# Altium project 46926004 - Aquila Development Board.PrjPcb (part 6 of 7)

## Sheet 160_Power_4.SchDoc: Aquila Development Board
size Letter; Organization: Toradex Solutions Inc.; Address1: 6415 Northwest Drive; Address2: Mississauga, ON, L4V 1X1; Address3: Canada; SheetNumber: 6; SheetTotal: 34
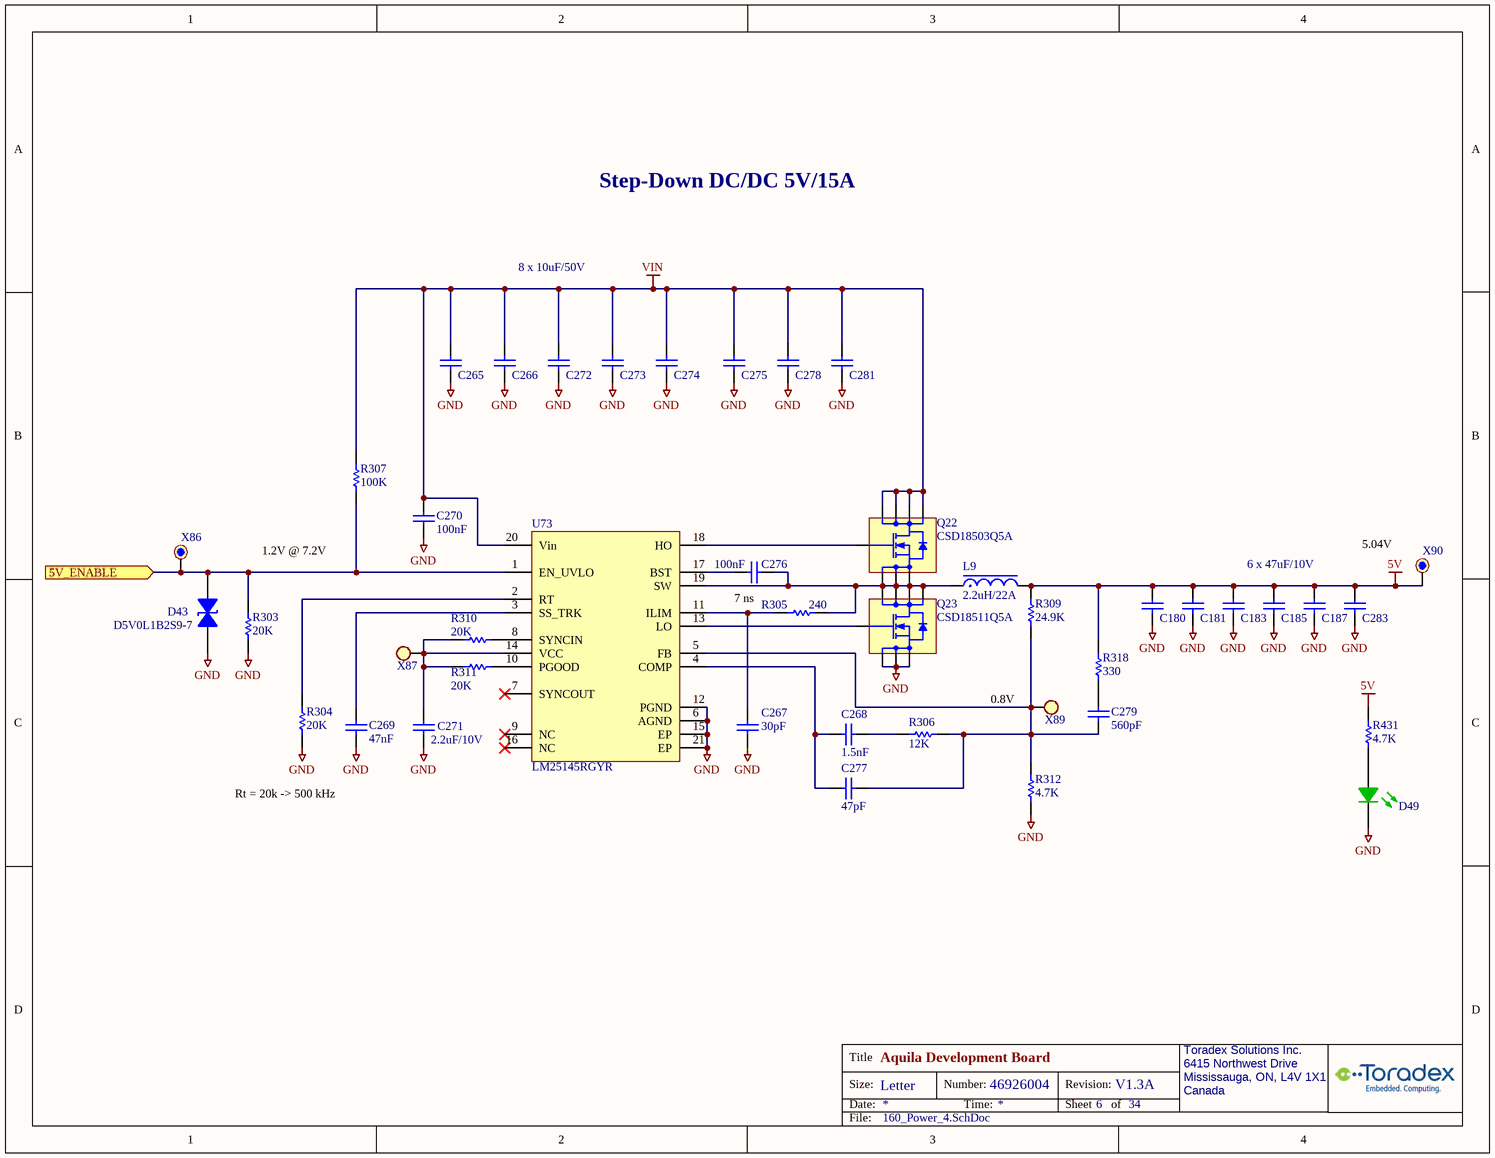
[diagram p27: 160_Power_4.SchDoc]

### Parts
C180  1941-Cap-1206-47uF/10V  [C/1206]  (value not drawn)
C181  1941-Cap-1206-47uF/10V  [C/1206]  (value not drawn)
C183  1941-Cap-1206-47uF/10V  [C/1206]  (value not drawn)
C185  1941-Cap-1206-47uF/10V  [C/1206]  (value not drawn)
C187  1941-Cap-1206-47uF/10V  [C/1206]  (value not drawn)
C265  10uF/50V  [CAPC3225N]  (value not drawn)
C266  10uF/50V  [CAPC3225N]  (value not drawn)
C267  value 30pF  [C0402_CAPC1005L]  (hidden comment: 1554-Cap-0402-30pF)
C268  value 1.5nF  [C0402_CAPC1005L]  (hidden comment: 1573-Cap-0402-1.5nF)
C269  value 47nF  [C/0603]  (hidden comment: 0913-Cap-0603-47nF/50V-X7R)
C270  100nF  [C0402_CAPC1005L]
C271  value 2.2uF/10V  [C0402_CAPC1005L]  (hidden comment: 2234-Cap-0402-2.2uF/10V)
C272  10uF/50V  [CAPC3225N]  (value not drawn)
C273  10uF/50V  [CAPC3225N]  (value not drawn)
C274  10uF/50V  [CAPC3225N]  (value not drawn)
C275  10uF/50V  [CAPC3225N]  (value not drawn)
C276  100nF  [C0402_CAPC1005L]
C277  value 47pF  [C/0603]  (hidden comment: 1567-Cap-0603-47pF/100V)
C278  10uF/50V  [CAPC3225N]  (value not drawn)
C279  value 560pF  [C/0603]  (hidden comment: 1717-Cap-0603-560pF/25V)
C281  10uF/50V  [CAPC3225N]  (value not drawn)
C283  1941-Cap-1206-47uF/10V  [C/1206]  (value not drawn)
D43  D5V0L1B2S9-7  [SOD923_DIO]
D49  Status  [LED-SMT-0603_APT1608CGCK]  (value not drawn)
L9  value 2.2uH/22A  [IND_SRP1265A-LF_BRN]  (hidden comment: 2229-Ind-13.5x12.5-2.2uH/22A)
Q22  CSD18503Q5A  [VSONP-8 (5x6)]
Q23  CSD18511Q5A  [VSONP-8 (5x6)]
R303  value 20K  [R/0603]  (hidden comment: 1216-Res-0603-20K)
R304  value 20K  [R/0603]  (hidden comment: 1216-Res-0603-20K)
R305  value 240  [R0402_RESC1005L]  (hidden comment: 1016-Res-0402-240ohm)
R306  value 12K  [R0402_RESC1005L]  (hidden comment: 1537-Res-0402-12K)
R307  value 100K  [R0402_RESC1005L]  (hidden comment: 1977-Res-0402-100K)
R309  value 24.9K  [R/0603]  (hidden comment: 1144-Res-0603-24.9K)
R310  value 20K  [R/0603]  (hidden comment: 1216-Res-0603-20K)
R311  value 20K  [R/0603]  (hidden comment: 1216-Res-0603-20K)
R312  value 4.7K  [R0402_RESC1005L]  (hidden comment: 2233-Res-0402-4.7K)
R318  value 330  [R0402_RESC1005L]  (hidden comment: 1807-Res-0402-330Ohm)
R431  value 4.7K  [R0402_RESC1005L]  (hidden comment: 2233-Res-0402-4.7K)
U73  LM25145RGYR  [VQFN-20 (3.5x4.5)]
X86  000-TestPoint  [TestPoint_1]  (value not drawn)
X87  000-TestPoint2  [TestPoint_3]  (value not drawn)
X89  000-TestPoint2  [TestPoint_3]  (value not drawn)
X90  000-TestPoint  [TestPoint_1]  (value not drawn)

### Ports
5V_ENABLE (in)

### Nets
5V: C180.2 C181.2 C183.2 C185.2 C187.2 C283.2 L9.2 R309.1 R318.1 R431.2 X90.1
GND: C180.1 C181.1 C183.1 C185.1 C187.1 C265.1 C266.1 C267.2 C269.2 C270.2 C271.1 C272.1 C273.1 C274.1 C275.1 C278.1 C281.1 C283.1 D43.2 D49.2(K) Q23.1(S) Q23.2(S) Q23.3(S) R303.1 R304.1 R312.2 U73.6(AGND) U73.12(PGND) U73.15(EP) U73.21(EP)
VIN: C265.2 C266.2 C270.1 C272.2 C273.2 C274.2 C275.2 C278.2 C281.2 Q22.5(D) Q22.6(D) Q22.7(D) Q22.8(D) R307.2 U73.20(Vin)
5V_ENABLE: D43.1 R303.2 R307.1 U73.1(EN_UVLO) X86.1 ; port 5V_ENABLE
NetC267_1: C267.1 R305.1 U73.11(ILIM)
NetC268_1: C268.1 C277.1 U73.4(COMP)
NetC268_2: C268.2 R306.2
NetC269_1: C269.1 U73.3(SS_TRK)
NetC271_2: C271.2 R310.1 R311.1 U73.14(VCC) X87.1
NetC276_1: C276.1 L9.1 Q22.1(S) Q22.2(S) Q22.3(S) Q23.5(D) Q23.6(D) Q23.7(D) Q23.8(D) R305.2 U73.19(SW)
NetC276_2: C276.2 U73.17(BST)
NetC277_2: C277.2 C279.2 R306.1 R309.2 R312.1 U73.5(FB) X89.1
NetC279_1: C279.1 R318.2
NetD49_1: D49.1(A) R431.1
NetQ22_4: Q22.4(G) U73.18(HO)
NetQ23_4: Q23.4(G) U73.13(LO)
NetR304_2: R304.2 U73.2(RT)
NetR310_2: R310.2 U73.8(SYNCIN)
NetR311_2: R311.2 U73.10(PGOOD)

Not connected (* = marked no-connect by the designer): U73 7(SYNCOUT)* 9(NC)* 16(NC)*

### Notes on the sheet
- Step-Down DC/DC 5V/15A
- 8 x 10uF/50V
- 1.2V @ 7.2V
- 6 x 47uF/10V
- 5.04V
- 7 ns
- (near X89) 0.8V
- Rt = 20k -> 500 kHz

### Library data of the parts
C180 C181 C183 C185 C187 C283 = 1941-Cap-1206-47uF/10V: (-55 to 85 DegC) CAP CER 47UF 10V 20% X5R 1206; MfrNo: CL31A476MPHNNNE; Mfr: Samsung; PN: 1941
C265 C266 C272-C275 C278 C281 = 1607-Cap-1206-10uF/50V: (-55 to 85 DegC) CAP CER 10UF 50V 10% X5R 1206; Mfr: Samsung; MfrNo: CL31A106KBHNNNE; PN: 1607; Alt: CL31A106MBHNNNE,UMK316BBJ106ML-T,UMK316BBJ106KL-T,GRT31CR61H106ME01L,MSASU31LBB5106MTNA01
C267 = 1554-Cap-0402-30pF: (-55 to 125 DegC AEC) CAP CER 30PF 5% 50V C0G/NPO 0402; Mfr: Murata; MfrNo: GCM1555C1H300JA16D; PN: 1554; Alt: AC0402JRNPO9BN300,GCM1555C1H300GA16D,GCM1555C1H300FA16D
C268 = 1573-Cap-0402-1.5nF: (-55 to 125 DegC AEC) CAP CER 1.5nF 10% 50V X7R 0402; Mfr: Taiyo Yuden; MfrNo: UMK105B7152KVHF; Alt: UMK105BJ152KVHF,CL05B152KB5VPNC,GCM155R71H152KA37D; PN: 1573
C269 = 0913-Cap-0603-47nF/50V-X7R: (-55 to 125 DegC) CAP CER 0.047UF 50V X7R 0603; Mfr: TDK Corporation; MfrNo: C1608X7R1H473K080AA; Alt: CL10B473KB8NNNL ,CL10B473KB8NNND,CL10B473KB8SFNC,CL10B473KB8NNNC; PN: 913; Alt2: CL10B473KB8WPNC,CC0603KRX7R9BB473,C1608X7R1H473K080AA,CL10B473KB8NNNC
C270 C276 = 1566-Cap-0402-100nF/50V: (-55 to 125 DegC AEC) Cap Ceramic 0.1uF 50V X7R 10% 0402; MfrNo: GRT155R71H104KE01D; Mfr: Murata; Alt: CL05B104KB54PNC,GCM155R71H104ME02D,GCM155R71H104KE02D,GCM155R71H104KE02J; PN: 1566
C271 = 2234-Cap-0402-2.2uF/10V: (-55 to 85 DegC) CAP CER 2.2UF 10V 20% X5R 0402; Mfr: Yageo; MfrNo: CC0402MRX5R6BB225; PN: 2234
C277 = 1567-Cap-0603-47pF/100V: (-55 to 125 DegC AEC) Cap Ceramic 47pF 100V C0G/NP0 5% SMD 0603; Mfr: Samsung; MfrNo: CL10C470JC81PNC; Alt: C0603C470J1GACAUTO,06031A470J4T2A,GCM1885C2A470JA16D; PN: 1567
C279 = 1717-Cap-0603-560pF/25V: (-55 to 125 DegC) CAP CER 560PF 25V C0G/NPO 0603; Mfr: Yageo; MfrNo: CC0603JRNPO8BN561; PN: 1717
D43 = 1655-D5V0L1B2S9-7: (-65 to 155 DegC) TVS DIODE Vwm:5V Vcl:14V@6A SOD-923; Mfr: Diodes; PN: 1655
D49 = 0333-LED Green 0603: (-40 to 85 DegC) LED GREEN 0603 50mcd; MfrNo: APT1608CGCK; Mfr: Kingbright; Alt: 754-1357-1-ND; Alt2: 160-1834-1-ND; PN: 333; DR: 754-1116-6-ND; DR2: 604-APT1608CGCK
L9 = 2229-Ind-13.5x12.5-2.2uH/22A: (-50 to 150 DegC) FIXED IND 2.2UH 22A 4.2 mOHM 13.5x12.5x6.4mm; Mfr: Bourns; MfrNo: SRP1265A-2R2M; PN: 2229
Q22 = 2196-CSD18503Q5A: (-55 to 150 DegC) MOSFET N-CH 40V 19A Vth:1.8V Ron typ:4.3mohm@10V Vgsm:2.45V 8-VSONP (5x6); Mfr: Texas Instruments; PN: 2196
Q23 = 2195-CSD18511Q5A: (-55 to 150 DegC) MOSFET N-CH 40V 27A Vth:1.8V Ron typ:3.5mohm@4.5V Vgsm:2.45V 8-VSONP (5x6); Mfr: Texas Instruments; MfrNo: CSD18511Q5AT; PN: 2195
R303 R304 R310 R311 = 1216-Res-0603-20K: (-55 to 155 DegC) RES SMD 20K 1% 1/10W 0603 100ppm; Mfr: Bourns; MfrNo: CR0603-FX-2002ELF; Alt: RMCF0603FT20K0,CR0603-FX-2002ELF,RK73H1JTTD2002F,RC0603FR-0720KL; PN: 1216
R305 = 1016-Res-0402-240ohm: (-55 to 155 DegC) RES SMD 240 OHM 1% 1/16W 0402; Mfr: Yageo; MfrNo: RC0402FR-07240RL; Alt: RMCF0402FT240R,RC1005F241CS,AC0402FR-07240RL; PN: 1016; Desc: (-55 to 155 DegC) )RES SMD 240 OHM 1% 1/16W 0402
R306 = 1537-Res-0402-12K: (-55 to 155 DegC AEC) RES 12K OHM 1% 1/16W 100ppm 0402; MfrNo: RMCF0402FT12K0; Mfr: Stackpole Electronics; Alt: AC0402FR-0712KL,CRGCQ0402F12K; PN: 1537
R307 = 1977-Res-0402-100K: (-55 to 155 DegC) RES 100K OHM 1/16W 1% 0402 SMD; Mfr: Yageo; MfrNo: RC0402FR-07100KL; PN: 1977
R309 = 1144-Res-0603-24.9K: (-55 to 155 DegC) RES SMD 24.9K OHM 1% 1/10W 0603 100ppm; MfrNo: RMCF0603FT24K9; Mfr: Stackpole Electronics; Alt: CR0603-FX-2492ELF,RC0603FR-0724K9L; PN: 1144
R312 R431 = 2233-Res-0402-4.7K: (-55 to 155 DegC) RES 4.70K OHM 1/16W 1% 0402 100ppm; MfrNo: RC0402FR-074K7L; Mfr: Yageo; PN: 2233
R318 = 1807-Res-0402-330Ohm: (-55 to 155 DegC AEC) RES 330 OHM 1% 1/16W 100ppm 0402; Mfr: Stackpole Electronics; MfrNo: RMCF0402FT330R; PN: 1807
U73 = 2194-LM25145RGYR: (-40 to 125 DegC) IC REG BUCK 6-42V INPUT 20VFQFN 1MHz; Mfr: Texas Instruments; PN: 2194
X86 X90 = 000-TestPoint: TestPoint TH; Note: this is PCB footprint only, no parts to buy or assemble
X87 X89 = 000-TestPoint2: TestPoint SMD; Note: PCB footprint only, no parts to buy or assemble

## Sheet 510_ISO_CAN.SchDoc: Aquila Development Board
size Letter; Organization: Toradex Solutions Inc.; Address1: 6415 Northwest Drive; Address2: Mississauga, ON, L4V 1X1; Address3: Canada; SheetNumber: 27; SheetTotal: 34
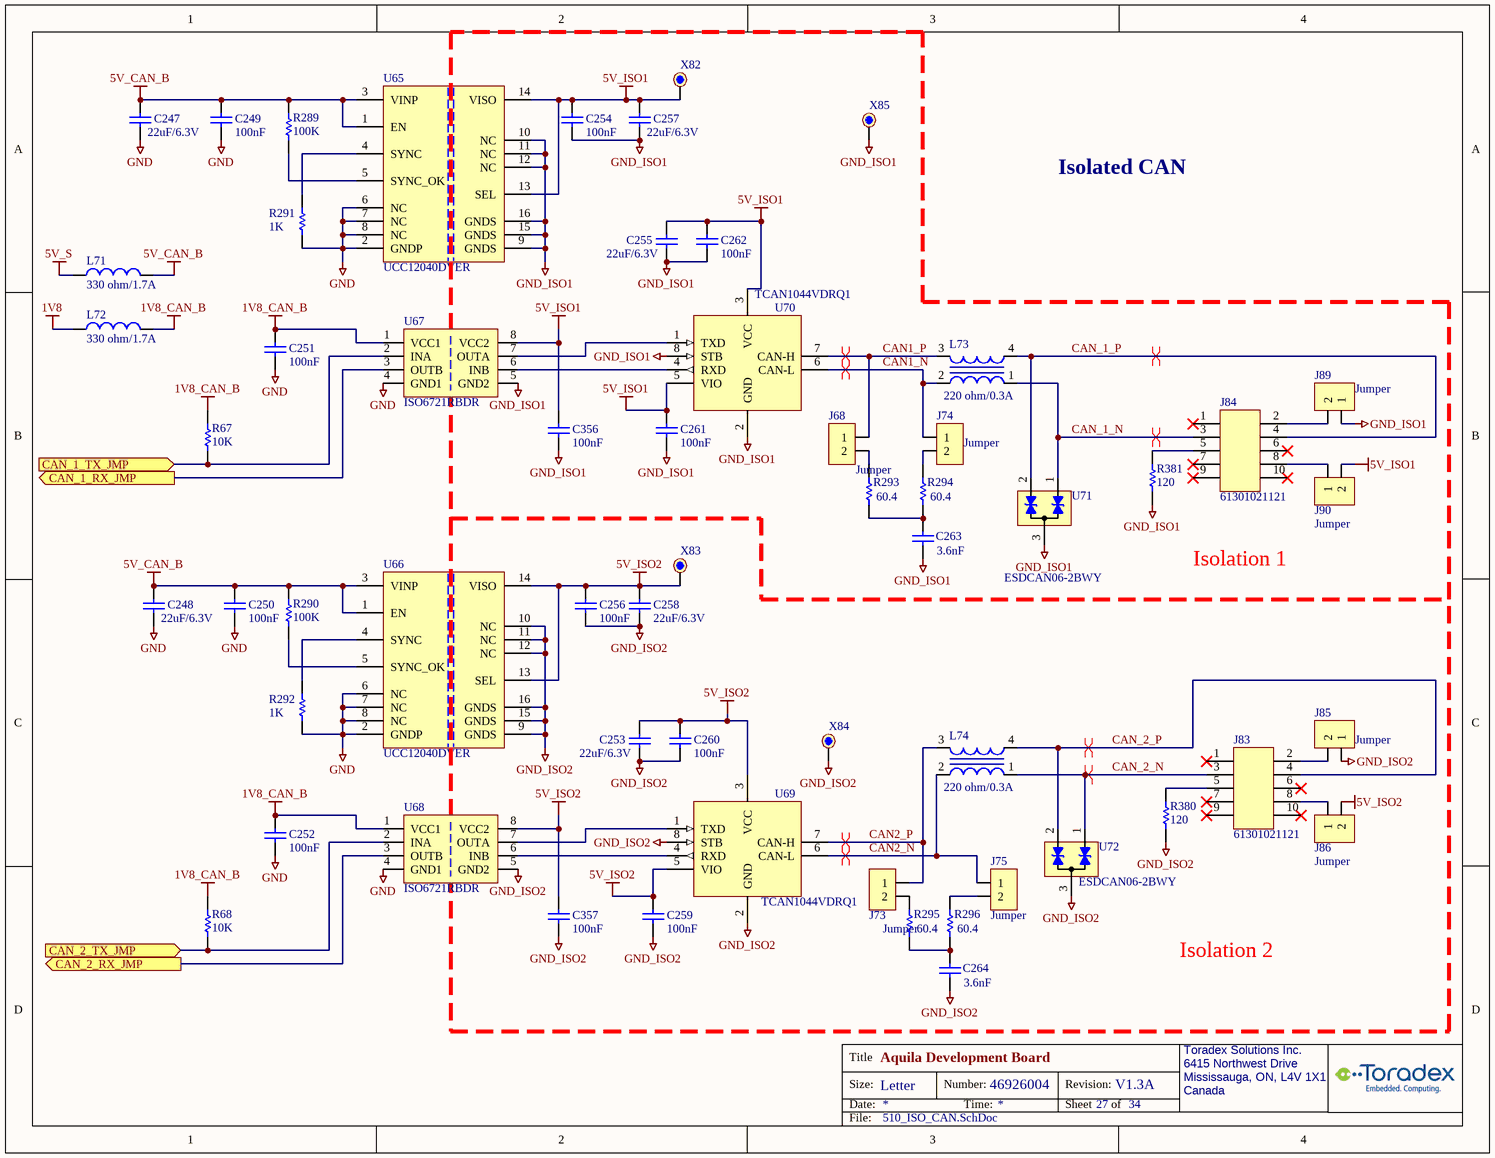
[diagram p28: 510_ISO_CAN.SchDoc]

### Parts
C247  22uF/6.3V  [C0402_CAPC1005L]
C248  22uF/6.3V  [C0402_CAPC1005L]
C249  100nF  [C0402_CAPC1005L]
C250  100nF  [C0402_CAPC1005L]
C251  100nF  [C0402_CAPC1005L]
C252  100nF  [C0402_CAPC1005L]
C253  22uF/6.3V  [C0402_CAPC1005L]
C254  100nF  [C0402_CAPC1005L]
C255  22uF/6.3V  [C0402_CAPC1005L]
C256  100nF  [C0402_CAPC1005L]
C257  22uF/6.3V  [C0402_CAPC1005L]
C258  22uF/6.3V  [C0402_CAPC1005L]
C259  100nF  [C0402_CAPC1005L]
C260  100nF  [C0402_CAPC1005L]
C261  100nF  [C0402_CAPC1005L]
C262  100nF  [C0402_CAPC1005L]
C263  value 3.6nF  [C/0603]  (hidden comment: 1470-Cap-0603-3.6nF)
C264  value 3.6nF  [C/0603]  (hidden comment: 1470-Cap-0603-3.6nF)
C356  100nF  [C0402_CAPC1005L]
C357  100nF  [C0402_CAPC1005L]
J68  67996-200HLF  [CON_HDR1X2]  (value not drawn)
J73  67996-200HLF  [CON_HDR1X2]  (value not drawn)
J74  67996-200HLF  [CON_HDR1X2]  (value not drawn)
J75  67996-200HLF  [CON_HDR1X2]  (value not drawn)
J83  61301021121  [WURTH_61301021121]
J84  61301021121  [WURTH_61301021121]
J85  67996-200HLF  [CON_HDR1X2]  (value not drawn)
J86  67996-200HLF  [CON_HDR1X2]  (value not drawn)
J89  67996-200HLF  [CON_HDR1X2]  (value not drawn)
J90  67996-200HLF  [CON_HDR1X2]  (value not drawn)
L71  value 330 ohm/1.7A  [C/0603]  (hidden comment: 0405-Fer-0603-330ohm/1.7A)
L72  value 330 ohm/1.7A  [C/0603]  (hidden comment: 0405-Fer-0603-330ohm/1.7A)
L73  220 ohm/0.3A  [COMMON_CHOKE_BOURNS_SRF2012-900YA]
L74  220 ohm/0.3A  [COMMON_CHOKE_BOURNS_SRF2012-900YA]
R67  value 10K  [R0402_RESC1005L]  (hidden comment: 1572-Res-0402-10K)
R68  value 10K  [R0402_RESC1005L]  (hidden comment: 1572-Res-0402-10K)
R289  value 100K  [R0402_RESC1005L]  (hidden comment: 1977-Res-0402-100K)
R290  value 100K  [R0402_RESC1005L]  (hidden comment: 1977-Res-0402-100K)
R291  value 1K  [R0402_RESC1005L]  (hidden comment: 1650-Res-0402-1K)
R292  value 1K  [R0402_RESC1005L]  (hidden comment: 1650-Res-0402-1K)
R293  value 60.4  [R/0603]  (hidden comment: 2199-Res-0603-60.4)
R294  value 60.4  [R/0603]  (hidden comment: 2199-Res-0603-60.4)
R295  value 60.4  [R/0603]  (hidden comment: 2199-Res-0603-60.4)
R296  value 60.4  [R/0603]  (hidden comment: 2199-Res-0603-60.4)
R380  value 120  [R0402_RESC1005L]  (hidden comment: 1552-Res-0402-120)
R381  value 120  [R0402_RESC1005L]  (hidden comment: 1552-Res-0402-120)
U65  UCC12040DVER  [SOIC-16]
U66  UCC12040DVER  [SOIC-16]
U67  ISO6721RBDR  [SOIC-8]
U68  ISO6721RBDR  [SOIC-8]
U69  TCAN1044VDRQ1  [SOIC-8]
U70  TCAN1044VDRQ1  [SOIC-8]
U71  ESDCAN06-2BWY  [SOT-323]
U72  ESDCAN06-2BWY  [SOT-323]
X82  000-TestPoint  [TestPoint_1]  (value not drawn)
X83  000-TestPoint  [TestPoint_1]  (value not drawn)
X84  000-TestPoint  [TestPoint_1]  (value not drawn)
X85  000-TestPoint  [TestPoint_1]  (value not drawn)

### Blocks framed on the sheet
Isolation 1: C254 C255 C257 C261-C263 C356 J68 J74 J84 J89 J90 L73 R293 R294 R381 U67 U70 U71 X82 X85

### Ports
CAN_1_RX_JMP (out), CAN_1_TX_JMP (in), CAN_2_RX_JMP (out), CAN_2_TX_JMP (in)

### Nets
1V8: L72.1
1V8_CAN_B: C251.2 C252.2 L72.2 R67.1 R68.1 U67.1(VCC1) U68.1(VCC1)
5V_CAN_B: C247.2 C248.2 C249.2 C250.2 L71.2 R289.2 R290.2 U65.1(EN) U65.3(VINP) U66.1(EN) U66.3(VINP)
5V_ISO1: C254.2 C255.2 C257.2 C261.2 C262.2 C356.2 J90.2 U65.13(SEL) U65.14(VISO) U67.8(VCC2) U70.3(VCC) U70.5(VIO) X82.1
5V_ISO2: C253.2 C256.2 C258.2 C259.2 C260.2 C357.2 J86.2 U66.13(SEL) U66.14(VISO) U68.8(VCC2) U69.3(VCC) U69.5(VIO) X83.1
5V_S: L71.1
GND: C247.1 C248.1 C249.1 C250.1 C251.1 C252.1 R291.1 R292.1 U65.2(GNDP) U65.6(NC) U65.7(NC) U65.8(NC) U66.2(GNDP) U66.6(NC) U66.7(NC) U66.8(NC) U67.4(GND1) U68.4(GND1)
GND_ISO1: C254.1 C255.1 C257.1 C261.1 C262.1 C263.2 C356.1 J89.1 R381.2 U65.9(GNDS) U65.10(NC) U65.11(NC) U65.12(NC) U65.15(GNDS) U65.16(GNDS) U67.5(GND2) U70.2(GND) U70.8(STB) U71.3 X85.1
GND_ISO2: C253.1 C256.1 C258.1 C259.1 C260.1 C264.2 C357.1 J85.1 R380.2 U66.9(GNDS) U66.10(NC) U66.11(NC) U66.12(NC) U66.15(GNDS) U66.16(GNDS) U68.5(GND2) U69.2(GND) U69.8(STB) U72.3 X84.1
CAN1_N: J74.1 L73.2 U70.6(CAN-L)
CAN1_P: J68.1 L73.3 U70.7(CAN-H)
CAN2_N: J75.1 L74.2 U69.6(CAN-L)
CAN2_P: J73.1 L74.3 U69.7(CAN-H)
CAN_1_N: J84.3 L73.1 U71.1
CAN_1_P: J84.4 L73.4 U71.2
CAN_1_RX_JMP: U67.3(OUTB) ; port CAN_1_RX_JMP
CAN_1_TX_JMP: R67.2 U67.2(INA) ; port CAN_1_TX_JMP
CAN_2_N: J83.3 L74.1 U72.1
CAN_2_P: J83.4 L74.4 U72.2
CAN_2_RX_JMP: U68.3(OUTB) ; port CAN_2_RX_JMP
CAN_2_TX_JMP: R68.2 U68.2(INA) ; port CAN_2_TX_JMP
NetC263_1: C263.1 R293.1 R294.1
NetC264_1: C264.1 R295.1 R296.1
NetJ68_2: J68.2 R293.2
NetJ73_2: J73.2 R295.2
NetJ74_2: J74.2 R294.2
NetJ75_2: J75.2 R296.2
NetJ83_2: J83.2 J85.2
NetJ83_5: J83.5 R380.1
NetJ83_8: J83.8 J86.1
NetJ84_2: J84.2 J89.2
NetJ84_5: J84.5 R381.1
NetJ84_8: J84.8 J90.1
NetR289_1: R289.1 U65.5(SYNC_OK)
NetR290_1: R290.1 U66.5(SYNC_OK)
NetR291_2: R291.2 U65.4(SYNC)
NetR292_2: R292.2 U66.4(SYNC)
NetU67_6: U67.6(INB) U70.4(RXD)
NetU67_7: U67.7(OUTA) U70.1(TXD)
NetU68_6: U68.6(INB) U69.4(RXD)
NetU68_7: U68.7(OUTA) U69.1(TXD)

Not connected (* = marked no-connect by the designer): J83 1* 6* 7* 9* 10*; J84 1* 6* 7* 9* 10*

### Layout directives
differential pair; differential pair class CAN: CAN1_N, CAN1_P, CAN2_N, CAN2_P, CAN_1_N, CAN_1_P, CAN_2_N, CAN_2_P

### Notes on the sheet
- Isolated CAN
- (near J89) Jumper
- Jumper
- (near J74) Jumper
- (near J90) Jumper
- (near J85) Jumper
- (near J75) Jumper
- Isolation 2

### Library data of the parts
C247 C248 C253 C255 C257 C258 = 2404-Cap-0402-22uF/6.3V: (-55 to 85 DegC) CAP CER 22UF 6.3V 20% X5R 0402; MfrNo: GRM155R60J226ME11D; Mfr: Murata; PN: 2404
C249-C252 C254 C256 C259-C262 C356 C357 = 1566-Cap-0402-100nF/50V: as C270 on sheet 160_Power_4
C263 C264 = 1470-Cap-0603-3.6nF: (-55 to 125 DegC) CAP CER 3600PF 50V C0G/NP0 0603; Mfr: Murata; MfrNo: GRM1885C1H362JA01D; Alt: GCM1885C1H362FA16J,C0603C362J5GAC7867,C0603C362F5GAC7867; PN: 1470
J68 J73-J75 J85 J86 J89 J90 = 1250-Conn-Hdr-1x2 TH Vert: (-40 to 85 DegC) CONN HDR VERT 1x2 2pos 2.54mm 0.1in Gold no-shroud; Mfr: Amphenol FCI; PN: 1250
J83 J84 = 2237-Conn-Hdr 2x10 2.54MM: (-40 to 105 DegC) CONN HEADER MALE VERT 2x5 10POS 2.54MM TH; Mfr: Wurth Electronics; PN: 2237
L71 L72 = 0405-Fer-0603-330ohm/1.7A: (-55 to 125 DegC) FERRITE BEAD 330 OHM 0603 1.7A 80mohm, typ 48mohm; Mfr: TDK Corporation; MfrNo: MPZ1608S331ATA00; PN: 405; TR: 445-5221-2-ND; DR: 445-5221-6-ND; DR2: 810-MPZ1608S331ATA00
L73 L74 = 1055-Ind-2x1.2-220ohm/0.4A-Choke: (-40 to 125 DegC) INDUCTOR COMMON MODE 220 OHM 0.3A 0.4ohm; MfrNo: SRF2012-221YA; Mfr: Bourns Inc.; PN: 1055; Alt: SRF2012-201YA
R67 R68 = 1572-Res-0402-10K: (-55 to 155 DegC AEC) RES 10K OHM 1% 1/16W 100ppm 0402; MfrNo: RMCF0402FT10K0; Mfr: Stackpole Electronics; Alt: AC0402FR-0710KL,AC0402FR-1310KL,CRGCQ0402F10K; PN: 1572
R289 R290 = 1977-Res-0402-100K: as R307 on sheet 160_Power_4
R291 R292 = 1650-Res-0402-1K: (-55 to 155 DegC AEC) RES 1K OHM 1% 1/16W 100ppm 0402; Mfr: TE Connectivity; MfrNo: CRGCQ0402F1K0; PN: 1650; Alt: CR0402AFX-1001GLF,AC0402FR-131KL,AC0402FR-071KL
R293-R296 = 2199-Res-0603-60.4: (-55 to 155 DegC) RES SMD 60.4 OHM 1% 1/10W 0603; Mfr: Bourns; MfrNo: CR0603-FX-60R4ELF; PN: 2199; Desc: (-55 to 155 DegC) RES SMD 60.4k OHM 1% 1/10W 0603
R380 R381 = 1552-Res-0402-120: (-55 to 155 DegC AEC) RES 120 OHM 1% 1/16W 100ppm 0402; MfrNo: RMCF0402FT120R; Mfr: Stackpole Electronics; PN: 1552; Alt: AC0402FR-07120RL,CRGCQ0402F120R
U65 U66 = 2065-UCC12040DVER: (-40 to 125 DegC) IC Isolated DC DC Converter-Output 3.3V, 5V 140mA, 4.5V-5.5V Input; Mfr: Texas Instruments; PN: 2065
U67 U68 = 2198-ISO6721RBDR: (-40 to 125 DegC) IC DGTL ISO GENERAL-PURPOSE, DUAL-CHANNEL, 1x In, 1x Out 1.71-5.5V; Mfr: Texas Instruments; PN: 2198
U69 U70 = 1620-TCAN1044VDRQ1: (-40 to 125 DegC) IC TXRX CAN FD 8MBPS Vio:1.8-5V Standby 8SOIC; Mfr: Texas Instruments; PN: 1620
U71 U72 = 1564-ESDCAN06-2BWY: (-55 to 175 DegC AEC) TVS DIODE CAN 2-ch 35V Vcl: 59Vmax, 8/20:3A, ESD:30KV air,30KV cont, 15pF, SOT323; Mfr: STMicroelectronics; PN: 1564
X82-X85 = 000-TestPoint: as X86 on sheet 160_Power_4

## Sheet 325_USB_PowerDelivery.SchDoc: Aquila Development Board
size Letter; Organization: Toradex Solutions Inc.; Address1: 6415 Northwest Drive; Address2: Mississauga, ON, L4V 1X1; Address3: Canada; SheetNumber: 18; SheetTotal: 34
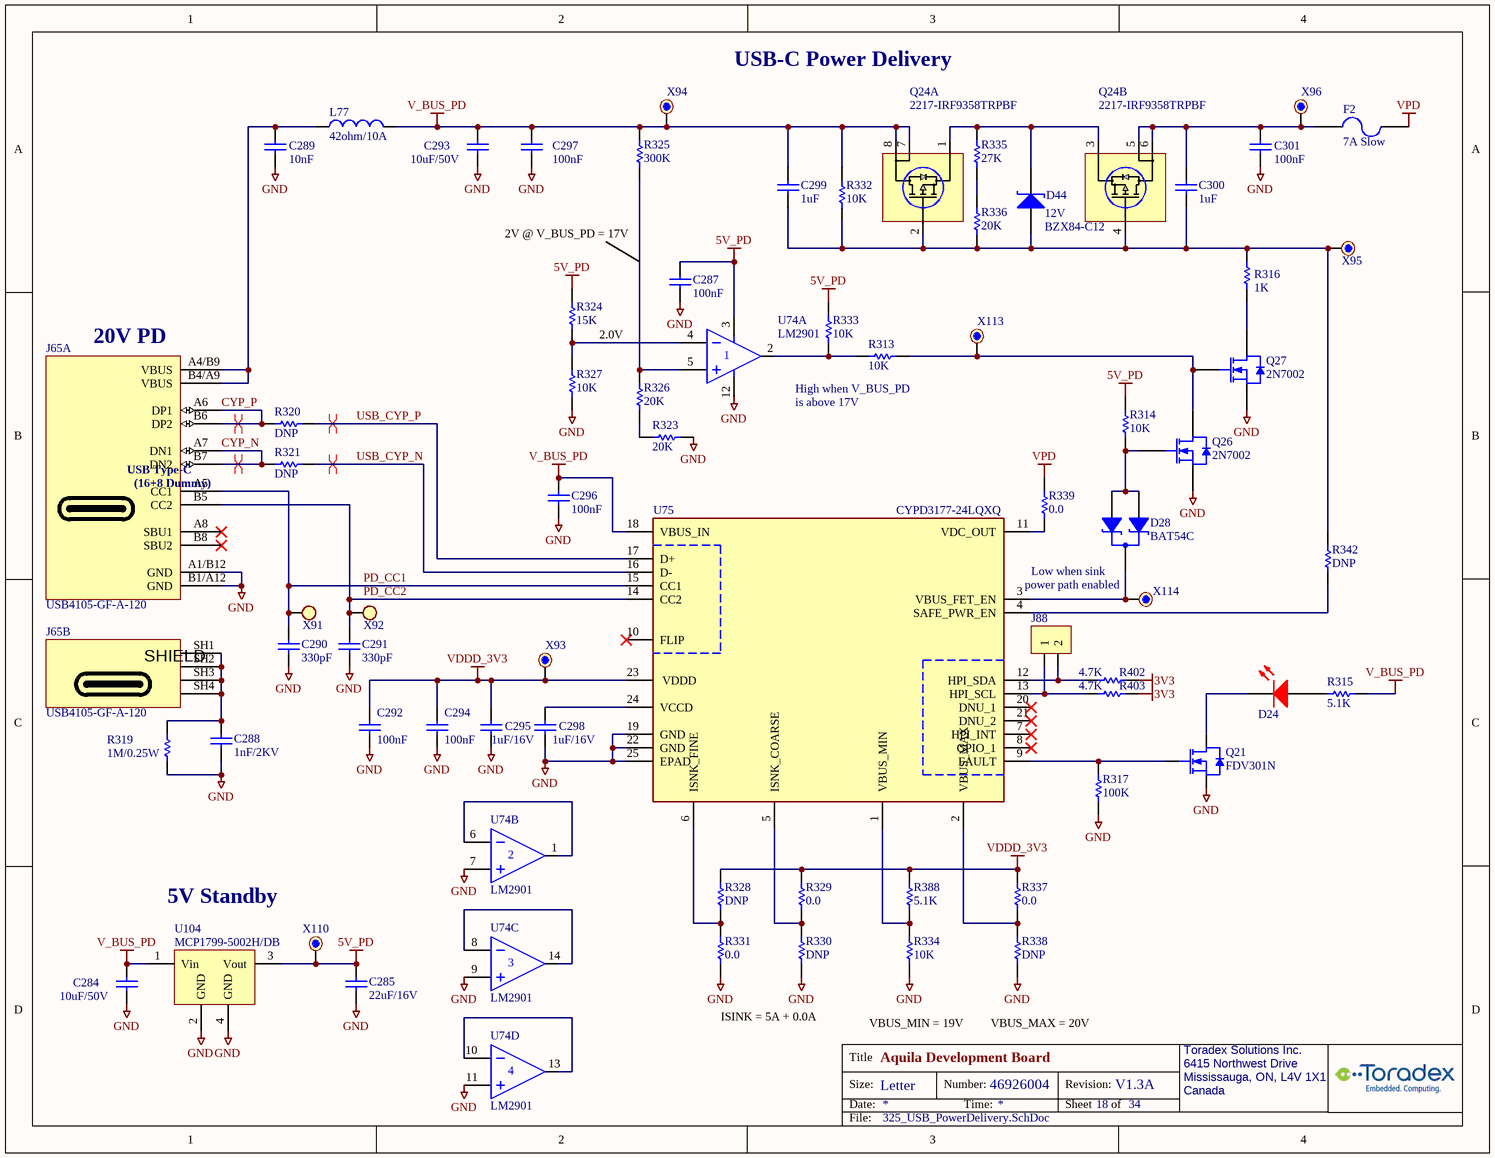
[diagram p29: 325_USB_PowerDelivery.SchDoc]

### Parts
C284  10uF/50V  [CAPC3225N]
C285  value 22uF/16V  [C/0805]  (hidden comment: 1314-Cap-0805-22uF/16V)
C287  100nF  [C0402_CAPC1005L]
C288  value 1nF/2KV  [C/1206]  (hidden comment: 0567-Cap-1206-1nF/2KV)
C289  10nF  [C0402_CAPC1005L]
C290  value 330pF  [C/0603]  (hidden comment: 0105-Cap-0603-330pF/100V)
C291  value 330pF  [C/0603]  (hidden comment: 0105-Cap-0603-330pF/100V)
C292  100nF  [C0402_CAPC1005L]
C293  10uF/50V  [CAPC3225N]
C294  100nF  [C0402_CAPC1005L]
C295  value 1uF/16V  [C0402_CAPC1005L]  (hidden comment: 1644-Cap-0402-1uF/16V)
C296  100nF  [C0402_CAPC1005L]
C297  100nF  [C0402_CAPC1005L]
C298  value 1uF/16V  [C0402_CAPC1005L]  (hidden comment: 1644-Cap-0402-1uF/16V)
C299  value 1uF  [C/0603]  (hidden comment: 1548-Cap-0603-1uF/50V)
C300  value 1uF  [C/0603]  (hidden comment: 1548-Cap-0603-1uF/50V)
C301  100nF  [C0402_CAPC1005L]
D24  Status  [LED-SMT-0603_APT1608CGCK]  (value not drawn)
D28  BAT54C  [SOT23_M]
D44  BZX84-C12  value 12V  [SOT23_N]
F2  7A Slow  [R/1206]
J65  USB4105-GF-A-120  [GCT_USB4105GFA120]  (parts A,B of 2)
J88  000-Hdr-2pin  [HDR1X2]  (value not drawn)  (no BOM)
L77  value 42ohm/10A  [FB_35F0121-0SR-10]  (hidden comment: 1652-Fer-42ohm/10A)
Q21  FDV301N  [SOT23]
Q24  2217-IRF9358TRPBF  [SOIC-8]  (parts A,B of 2)
Q26  2N7002  [SOT23]
Q27  2N7002  [SOT23]
R313  value 10K  [R0402_RESC1005L]  (hidden comment: 1572-Res-0402-10K)
R314  value 10K  [R0402_RESC1005L]  (hidden comment: 1572-Res-0402-10K)
R315  value 5.1K  [R/0603]  (hidden comment: 0227-Res-0603-5.1K)
R316  value 1K  [R0402_RESC1005L]  (hidden comment: 1650-Res-0402-1K)
R317  value 100K  [R0402_RESC1005L]  (hidden comment: 1977-Res-0402-100K)
R319  value 1M/0.25W  [R/1206]  (hidden comment: 1860-Res-1206-1M-5%-0.25W)
R320  value DNP  [R/0603]  (hidden comment: 0000-Res-0603-DNP)
R321  value DNP  [R/0603]  (hidden comment: 0000-Res-0603-DNP)
R323  value 20K  [R/0603]  (hidden comment: 1216-Res-0603-20K)
R324  value 15K  [R0402_RESC1005L]  (hidden comment: 1550-Res-0402-15K)
R325  value 300K  [R/0603]  (hidden comment: 0176-Res-0603-300K)
R326  value 20K  [R/0603]  (hidden comment: 1216-Res-0603-20K)
R327  value 10K  [R0402_RESC1005L]  (hidden comment: 1572-Res-0402-10K)
R328  value DNP  [R/0603]  (hidden comment: 0000-Res-0603-DNP)
R329  value 0.0  [R/0603]  (hidden comment: 0195-Res-0603-0.0ohm)
R330  value DNP  [R/0603]  (hidden comment: 0000-Res-0603-DNP)
R331  value 0.0  [R/0603]  (hidden comment: 0195-Res-0603-0.0ohm)
R332  value 10K  [R0402_RESC1005L]  (hidden comment: 1572-Res-0402-10K)
R333  value 10K  [R0402_RESC1005L]  (hidden comment: 1572-Res-0402-10K)
R334  value 10K  [R0402_RESC1005L]  (hidden comment: 1572-Res-0402-10K)
R335  value 27K  [R0402_RESC1005L]  (hidden comment: 1538-Res-0402-27k)
R336  value 20K  [R/0603]  (hidden comment: 1216-Res-0603-20K)
R337  value 0.0  [R/0603]  (hidden comment: 0195-Res-0603-0.0ohm)
R338  value DNP  [R/0603]  (hidden comment: 0000-Res-0603-DNP)
R339  value 0.0  [R/0603]  (hidden comment: 0195-Res-0603-0.0ohm)
R342  value DNP  [R/0603]  (hidden comment: 0000-Res-0603-DNP)
R388  value 5.1K  [R/0603]  (hidden comment: 0227-Res-0603-5.1K)
R402  value 4.7K  [R0402_RESC1005L]  (hidden comment: 2233-Res-0402-4.7K)
R403  value 4.7K  [R0402_RESC1005L]  (hidden comment: 2233-Res-0402-4.7K)
U74  LM2901  [PW014_N]  (parts A,B,C,D of 4)
U75  CYPD3177-24LQXQ  [IC-Cypress-CYPD3177-24LQXQ]
U104  MCP1799-5002H/DB  [SOT223]
X91  000-TestPoint2  [TestPoint_3]  (value not drawn)
X92  000-TestPoint2  [TestPoint_3]  (value not drawn)
X93  000-TestPoint  [TestPoint_1]  (value not drawn)
X94  000-TestPoint  [TestPoint_1]  (value not drawn)
X95  000-TestPoint  [TestPoint_1]  (value not drawn)
X96  000-TestPoint  [TestPoint_1]  (value not drawn)
X110  000-TestPoint  [TestPoint_1]  (value not drawn)
X113  000-TestPoint  [TestPoint_1]  (value not drawn)
X114  000-TestPoint  [TestPoint_1]  (value not drawn)

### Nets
3V3: R402.1 R403.1
5V_PD: C285.2 C287.2 R314.2 R324.2 R333.2 U74.3(VCC) U104.3(Vout) X110.1
GND: C284.1 C285.1 C287.1 C288.1 C289.1 C290.2 C291.2 C292.1 C293.1 C294.1 C295.1 C296.1 C297.1 C298.1 C301.1 J65.A1/B12(GND) J65.B1/A12(GND) Q21.2(S) Q26.2(S) Q27.2(S) R317.1 R319.2 R323.2 R327.2 R330.1 R331.2 R334.1 R338.1 U74.7(IN+) U74.9(IN+) U74.11(IN+) U74.12(GND) U75.19(GND) U75.22(GND) U75.25(EPAD) U104.2(GND) U104.4(GND)
V_BUS_PD: C284.2 C293.2 C296.2 C297.2 C299.1 L77.2 Q24.7 Q24.8 R315.2 R325.1 R332.2 U75.18(VBUS_IN) U104.1(Vin) X94.1
VDDD_3V3: C292.2 C294.2 C295.2 R328.2 R329.1 R337.2 R388.1 U75.23(VDDD) X93.1
VPD: F2.2 R339.1
CYP_N: J65.A7(DN1) J65.B7(DN2) R321.2
CYP_P: J65.A6(DP1) J65.B6(DP2) R320.2
PD_CC1: C290.1 J65.A5(CC1) U75.15(CC1) X91.1
PD_CC2: C291.1 J65.B5(CC2) U75.14(CC2) X92.1
USB_CYP_N: R321.1 U75.16(D-)
USB_CYP_P: R320.1 U75.17(D+)
NetC288_2: C288.2 J65.SH1(SHIELD) J65.SH2(SHIELD) J65.SH3(SHIELD) J65.SH4(SHIELD) R319.1
NetC289_2: C289.2 J65.A4/B9(VBUS) J65.B4/A9(VBUS) L77.1
NetC298_2: C298.2 U75.24(VCCD)
NetC299_2: C299.2 C300.2 D44.1(A) Q24.2 Q24.4 R316.1 R332.1 R336.1 R342.2 X95.1
NetC300_1: C300.1 C301.2 F2.1 Q24.5 Q24.6 X96.1
NetD24_1: D24.1(A) R315.1
NetD24_2: D24.2(K) Q21.3(D)
NetD28_1: D28.1(A1) D28.2(A2) Q26.1(G) R314.1
NetD28_3: D28.3(K) U75.3(VBUS_FET_EN) X114.1
NetD44_3: D44.3(K) Q24.1 Q24.3 R335.2
NetJ88_1: J88.1 R403.2 U75.13(HPI_SCL)
NetJ88_2: J88.2 R402.2 U75.12(HPI_SDA)
NetQ21_1: Q21.1(G) R317.2 U75.9(FAULT)
NetQ26_3: Q26.3(D) Q27.1(G) R313.1 X113.1
NetQ27_3: Q27.3(D) R316.2
NetR313_2: R313.2 R333.1 U74.2(OUT)
NetR323_1: R323.1 R326.2
NetR324_1: R324.1 R327.1 U74.4(IN-)
NetR325_2: R325.2 R326.1 U74.5(IN+)
NetR328_1: R328.1 R331.1 U75.6(ISNK_FINE)
NetR329_2: R329.2 R330.2 U75.5(ISNK_COARSE)
NetR334_2: R334.2 R388.2 U75.1(VBUS_MIN)
NetR335_1: R335.1 R336.2
NetR337_1: R337.1 R338.2 U75.2(VBUS_MAX)
NetR339_2: R339.2 U75.11(VDC_OUT)
NetR342_1: R342.1 U75.4(SAFE_PWR_EN)
NetU74_1: U74.1(OUT) U74.6(IN-)
NetU74_8: U74.8(IN-) U74.14(OUT)
NetU74_10: U74.10(IN-) U74.13(OUT)

Not connected (* = marked no-connect by the designer): J65 A8(SBU1)* B8(SBU2)*; U75 7(HPI_INT)* 8(GPIO_1)* 10(FLIP)* 20(DNU_1)* 21(DNU_2)*

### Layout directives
differential pair; differential pair class USB_CYP: CYP_N, CYP_P, USB_CYP_N, USB_CYP_P

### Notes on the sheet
- USB-C Power Delivery
- 2V @ V_BUS_PD = 17V
- (near J65) 20V PD
- 2.0V
- High when V_BUS_PD
- is above 17V
- power path enabled
- Low when sink
- 5V Standby
- ISINK = 5A + 0.0A
- VBUS_MIN = 19V
- VBUS_MAX = 20V

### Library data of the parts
C284 C293 = 1607-Cap-1206-10uF/50V: (-55 to 85 DegC) CAP CER 10UF 50V 10% X5R 1206; Mfr: Samsung; MfrNo: CL31A106KBHNNNE; Alt: CL31A106MBHNNNE,UMK316BBJ106ML-T,UMK316BBJ106KL-T,GRT31CR61H106ME01L,MSASU31LBB5106MTNA01; PN: 1607
C285 = 1314-Cap-0805-22uF/16V: (-55 to 85 DegC) CAP CER 22uF 16V X5R 0805; MfrNo: CL21A226MOQNNNE; Mfr: Samsung; PN: 1314; Alt: CL21A226MOCLRNC,CL21A226KOQNNNG,GRM21BR61C226ME44L,EMK212BBJ226MG-T
C287 C292 C294 C296 C297 C301 = 1566-Cap-0402-100nF/50V: as C270 on sheet 160_Power_4
C288 = 0567-Cap-1206-1nF/2KV: (-55 to 125 DegC) CAP CER 1000PF 2KV X7R 1206; Mfr: Johanson Dielectrics Inc.; MfrNo: 202R18W102KV4E; PN: 567; Alt: 478-2956-1-ND; Alt2: 399-4819-1-ND
C289 = 1149-Cap-0402-10nF/50V: (-55 to 125 DegC) Cap Ceramic 10nF 50V X7R 10% 0402; Mfr: Yageo; MfrNo: CC0402KRX7R9BB103; PN: 1149; Alt: CL05B103KB5NNNC,UMK105BJ103KV-F,CL05B103KB5NFNC,0402B103K500CT,CC0402KRX7R9BB103
C290 C291 = 0105-Cap-0603-330pF/100V: (-55 to 125 DegC) CAP CER 330PF 100V 5% NP0 0603; Mfr: Samsung; MfrNo: CL10C331JC8NNNC; Alt: 1276-1073-1-ND; Alt2: 399-1068-1-ND; PN: 105
C295 C298 = 1644-Cap-0402-1uF/16V: (-55 to 85 DegC) CAP CER 1UF 16V 20% X5R 0402; Mfr: Murata; MfrNo: GRM155R61C105MA12D; PN: 1644; Alt: GRM155R61C105KA12D,CL05A105KO5NNNC
C299 C300 = 1548-Cap-0603-1uF/50V: (-55 to 85 DegC AEC) CAP CER 1UF 50V X7R 0603; MfrNo: GRT188R61H105ME13D; Mfr: Murata; PN: 1548; Alt: UMK107ABJ105KAHT,MCASU168AB5105KTNA01,MCASU168AB5105KTNA1J,GRT188R61H105KE13D,UMK107ABJ105MAHT,CGA3E3X5R1H105K080AB
D24 = 1859-LED Red 0603: (-30 to 85 DegC) LED RED 0603 99mcd Vf:2.0V; Mfr: Vishay Lite-On; MfrNo: LTST-C190KRKT; Alt: PN331; PN: 1859
D28 = 0242B-BAT54C: (-55 to 125 DegC) DIODE SCHOTTKY 30V 200MA SOT23, comm. Cathode; Mfr: ON Semi; MfrNo: BAT54CLT1G; Alt: BAT54CFSCT-ND; Alt2: BAT54C-FDICT-ND; PN: 242; TR: BAT54CLT1GOSTR-ND; DR: BAT54CLT1GOSDKR-ND; DR2: 863-BAT54CLT1G
D44 = 0210-BZX84-C12: (-65 to 150 DegC) DIODE ZENER 12V 225MW SOT23-3; Mfr: On Semi; MfrNo: BZX84C12LT1G; PN: 210; Alt: 568-1674-1-ND; Alt2: BZX84C12-TPMSCT-ND
F2 = 1336-Fuse 7A Slow: (-55 to 125 DegC) FUSE SLOW 63VDC 6A 1206 14.5mohm; MfrNo: 0685T6000-01; Mfr: Bel; PN: 1336
J65 = 1660-Conn-USB-Type-C: (-40 to 85 DegC) Conn USB TYPE C RA, 24 (16+8 Dummy) Position, SMT/TH; Mfr: Global Connector Technology; Desc: (-40 to 85 DegC) Conn USB TYPE C RA SMT/TH; PN: 1660
J88 = 000-Hdr-2pin: Header, 2-Pin; Note: PCB footprint only, no parts to buy or assemble
L77 = 1652-Fer-42ohm/10A: (-55 to 125 DegC AEC) FERRITE BEAD 42ohm 10A 0.75mohm 3x3mm SMD; Mfr: Laird Steward; MfrNo: 35F0121-0SR-10; PN: 1652
Q21 = 0761-FDV301N: (-55 to 155 DegC) MOSFET N-CH 25V 220MA SOT-23 Vth:1.1V Ron typ:4ohm@3V Vgsm:8V; Mfr: Fairchild/ON Semiconductor; PN: 761; DR: FDV301NDKR-ND; TR: FDV301NTR-ND; Alt: DMN62D0U-13, DMN62D0U-7, DMN61D9U-7
Q24 = 2217-IRF9358TRPBF: (-55 to 150 DegC) MOSFET 2P-CH 30V 9.2A 8SO; Mfr: Infineon Technologies; PN: 2217
Q26 Q27 = 0030-2N7002: (-55 to 150 DegC AEC) MOSFET N-CH SGL 60V SOT-23 0.3A 1.3ohm@5V; Mfr: NXP; MfrNo: 2N7002P,215; Alt: 2N7002ET1GOSCT-ND; Alt2: 2N7002-FDICT-ND; PN: 30; TR: 568-5818-2-ND; DR: 568-5818-6-ND; DR2: 771-2N7002P-215
R313 R314 R327 R332-R334 = 1572-Res-0402-10K: as R67 on sheet 510_ISO_CAN
R315 R388 = 0227-Res-0603-5.1K: (-55 to 155 DegC) RES 5.1K OHM 1/10W 1% 0603 SMD; Mfr: Rohm; MfrNo: MCR03ERTF5101; Alt: 1276-4713-1-ND; Alt2: 311-5.10KHRCT-ND; PN: 227
R316 = 1650-Res-0402-1K: (-55 to 155 DegC AEC) RES 1K OHM 1% 1/16W 100ppm 0402; MfrNo: CRGCQ0402F1K0; Mfr: TE Connectivity; Alt: CR0402AFX-1001GLF,AC0402FR-131KL,AC0402FR-071KL; PN: 1650
R317 = 1977-Res-0402-100K: as R307 on sheet 160_Power_4
R319 = 1860-Res-1206-1M-5%-0.25W: (-55 to 155 DegC) RES SMD 1M OHM 5% 0.25W 10ppm 1206; Mfr: TE Connectivity; MfrNo: CRGCQ1206J1M0; PN: 1860; Alt: RMCF1206JT1M00, RMCF1206JG1M00, CR1206-JW-105ELF
R320 R321 R328 R330 R338 R342 = 0000-Res-0603-DNP: RES 0603
R323 R326 R336 = 1216-Res-0603-20K: as R303 on sheet 160_Power_4
R324 = 1550-Res-0402-15K: (-55 to 155 DegC AEC) RES 15K OHM 1% 1/16W 100ppm 0402; Mfr: Stackpole Electronics; MfrNo: RMCF0402FT15K0; Alt: AC0402FR-0715KL,CRGCQ0402F15K; PN: 1550
R325 = 0176-Res-0603-300K: (-55 to 155 DegC) RES 300K OHM 1/10W 1% 0603 SMD; Mfr: Yageo; MfrNo: RC0603FR-07300KL; Alt: RHM300KCFCT-ND; Alt2: P300KHCT-ND; PN: 176; TR: 311-300KHRTR-ND
R329 R331 R339 = 0195-Res-0603-0.0ohm: (-55 to 155 DegC) RES 0.0 OHM 1/10W JUMP 0603; Mfr: Samsung; MfrNo: RC1608J000CS; Alt: 311-0.0GRCT-ND; Alt2: A106051CT-ND; PN: 195; TR: 1276-3510-2-ND
R335 = 1538-Res-0402-27k: (-55 to 155 DegC AEC) RES 27K OHM 1% 1/16W 100ppm 0402; Mfr: Stackpole Electronics; MfrNo: RMCF0402FT27K0; PN: 1538; Alt: AC0402FR-0727KL,CRGCQ0402F27K
R337 = 0195-Res-0603-0.0ohm: (-55 to 155 DegC) RES 0.0 OHM 1/10W JUMP 0603; Mfr: Samsung; MfrNo: RC1608J000CS; PN: 195; Alt: 311-0.0GRCT-ND; Alt2: A106051CT-ND; TR: 1276-3510-2-ND
R402 R403 = 2233-Res-0402-4.7K: as R312 on sheet 160_Power_4
U74 = 0236-LM2901: (-40 to 125 DegC) IC COMPARATOR QUAD LP 14-TSSOP 2-30V OC Iq:1.3mAtyp 2.5mAmax Vos:1mVtyp 15mVmax Ib:25nAtyp 400nAmax; Mfr: ST; MfrNo: LM2901PT; Alt: 296-6597-1-ND; PN: 236; DR: 497-6454-6-ND; TR: 497-6454-2-ND; DR2: 511-LM2901P
U75 = 2216-CYPD3177-24LQXQ: (-40 to 125 DegC) IC USB Type C PMIC 20V/5A Max 24-QFN (4x4); Mfr: Infineon Technologies; PN: 2216
U104 = 1666-MCP1799: (-40 to 150 DegC) IC REG LINEAR LDO Vin: 45Vmax Vout:5V fixed 80mA SOT223-3; Mfr: Microchip; MfrNo: MCP1799T-5002H/DB; PN: 1666; Note: same component in tubes: MCP1799-5002H/DB
X91 X92 = 000-TestPoint2: as X87 on sheet 160_Power_4
X93-X96 X110 X113 X114 = 000-TestPoint: as X86 on sheet 160_Power_4

## Sheet 700_RS232_RS485.SchDoc: Aquila Development Board
size Letter; Organization: Toradex Solutions Inc.; Address1: 6415 Northwest Drive; Address2: Mississauga, ON, L4V 1X1; Address3: Canada; SheetNumber: 31; SheetTotal: 34
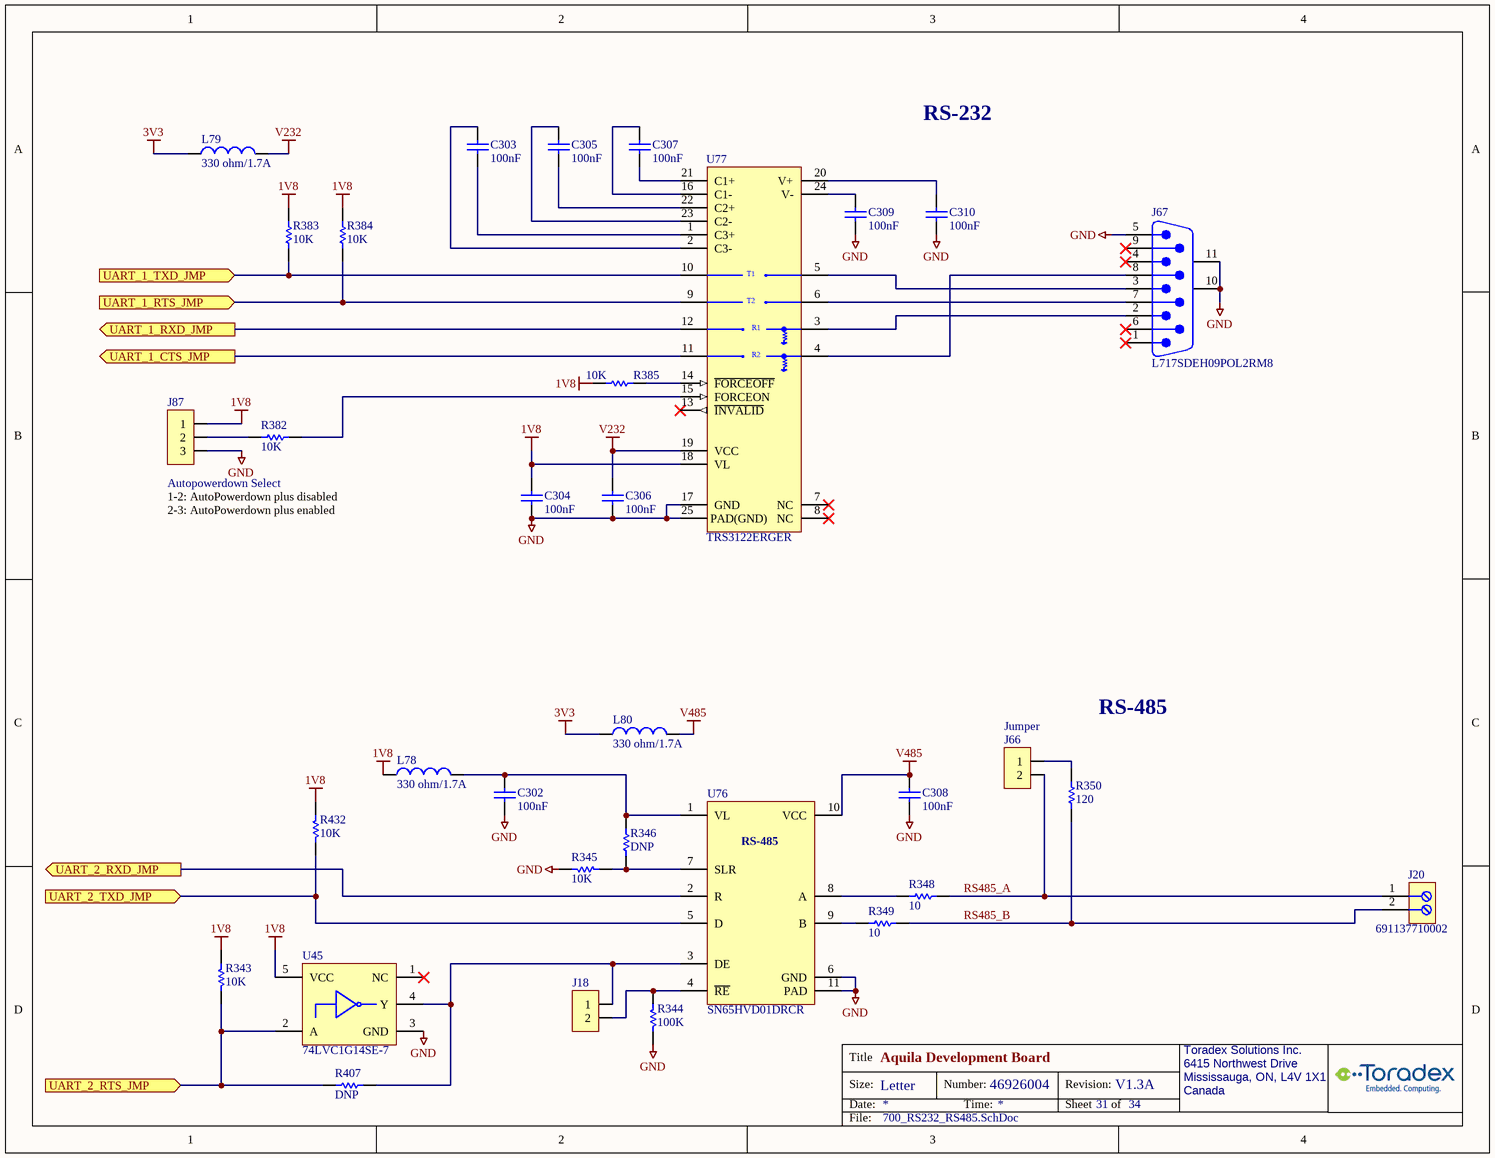
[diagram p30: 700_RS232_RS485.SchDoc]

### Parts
C302  100nF  [C0402_CAPC1005L]
C303  100nF  [C0402_CAPC1005L]
C304  100nF  [C0402_CAPC1005L]
C305  100nF  [C0402_CAPC1005L]
C306  100nF  [C0402_CAPC1005L]
C307  100nF  [C0402_CAPC1005L]
C308  100nF  [C0402_CAPC1005L]
C309  100nF  [C0402_CAPC1005L]
C310  100nF  [C0402_CAPC1005L]
J18  1250-Conn-Hdr-1x2 TH Vert  [CON_HDR1X2]  (value not drawn)
J20  691137710002  [WURTH_691137710002]
J66  67996-200HLF  [CON_HDR1X2]  (value not drawn)
J67  L717SDEH09POL2RM8  [DSUB_A-DS 09 A/KG-T2S]
J87  68001-203HLF  [CON_HDR1X3]  (value not drawn)
L78  value 330 ohm/1.7A  [C/0603]  (hidden comment: 0405-Fer-0603-330ohm/1.7A)
L79  value 330 ohm/1.7A  [C/0603]  (hidden comment: 0405-Fer-0603-330ohm/1.7A)
L80  value 330 ohm/1.7A  [C/0603]  (hidden comment: 0405-Fer-0603-330ohm/1.7A)
R343  value 10K  [R0402_RESC1005L]  (hidden comment: 1572-Res-0402-10K)
R344  value 100K  [R0402_RESC1005L]  (hidden comment: 1977-Res-0402-100K)
R345  value 10K  [R0402_RESC1005L]  (hidden comment: 1572-Res-0402-10K)
R346  value DNP  [R/0603]  (hidden comment: 0000-Res-0603-DNP)
R348  value 10  [R0402_RESC1005L]  (hidden comment: 0257-Res-0402-10ohm)
R349  value 10  [R0402_RESC1005L]  (hidden comment: 0257-Res-0402-10ohm)
R350  value 120  [R0402_RESC1005L]  (hidden comment: 1552-Res-0402-120)
R382  value 10K  [R0402_RESC1005L]  (hidden comment: 1572-Res-0402-10K)
R383  value 10K  [R0402_RESC1005L]  (hidden comment: 1572-Res-0402-10K)
R384  value 10K  [R0402_RESC1005L]  (hidden comment: 1572-Res-0402-10K)
R385  value 10K  [R0402_RESC1005L]  (hidden comment: 1572-Res-0402-10K)
R407  value DNP  [R/0603]  (hidden comment: 0000-Res-0603-DNP)
R432  value 10K  [R0402_RESC1005L]  (hidden comment: 1572-Res-0402-10K)
U45  74LVC1G14SE-7  [SOT353-5N]
U76  SN65HVD01DRCR  [10-VSON (3x3)]
U77  TRS3122ERGER  [QFN4X4-24_EP]

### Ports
UART_1_CTS_JMP (out), UART_1_RTS_JMP (in), UART_1_RXD_JMP (out), UART_1_TXD_JMP (in), UART_2_RTS_JMP (in), UART_2_RXD_JMP (out), UART_2_TXD_JMP (in)

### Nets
1V8: C304.1 J87.1 L78.1 R343.2 R383.2 R384.2 R385.2 R432.2 U45.5(VCC) U77.18(VL)
3V3: L79.1 L80.1
GND: C302.1 C304.2 C306.2 C308.2 C309.2 C310.2 J67.5 J67.10(MH1) J67.11(MH2) J87.3 R344.1 R345.1 U45.3(GND) U76.6(GND) U76.11(PAD) U77.17(GND) U77.25(PAD(GND))
V232: C306.1 L79.2 U77.19(VCC)
V485: C308.1 L80.2 U76.10(VCC)
RS485_A: J20.1 J66.2 R348.1
RS485_B: J20.2 R349.1 R350.2
UART_1_CTS_JMP: U77.11(ROUT2) ; port UART_1_CTS_JMP
UART_1_RTS_JMP: R384.1 U77.9(DIN2) ; port UART_1_RTS_JMP
UART_1_RXD_JMP: U77.12(ROUT1) ; port UART_1_RXD_JMP
UART_1_TXD_JMP: R383.1 U77.10(DIN1) ; port UART_1_TXD_JMP
UART_2_RTS_JMP: R343.1 R407.2 U45.2(A) ; port UART_2_RTS_JMP
UART_2_RXD_JMP: U76.2(R) ; port UART_2_RXD_JMP
UART_2_TXD_JMP: R432.1 U76.5(D) ; port UART_2_TXD_JMP
NetC302_2: C302.2 L78.2 R346.2 U76.1(VL)
NetC303_1: C303.1 U77.2(C3-)
NetC303_2: C303.2 U77.1(C3+)
NetC305_1: C305.1 U77.23(C2-)
NetC305_2: C305.2 U77.22(C2+)
NetC307_1: C307.1 U77.16(C1-)
NetC307_2: C307.2 U77.21(C1+)
NetC309_1: C309.1 U77.24(V-)
NetC310_1: C310.1 U77.20(V+)
NetJ18_1: J18.1 R407.1 U45.4(Y) U76.3(DE)
NetJ18_2: J18.2 R344.2 U76.4(~{RE})
NetJ66_1: J66.1 R350.1
NetJ67_2: J67.2 U77.3(RIN1)
NetJ67_3: J67.3 U77.5(DOUT1)
NetJ67_7: J67.7 U77.6(DOUT2)
NetJ67_8: J67.8 U77.4(RIN2)
NetJ87_2: J87.2 R382.2
NetR345_2: R345.2 R346.1 U76.7(SLR)
NetR348_2: R348.2 U76.8(A)
NetR349_2: R349.2 U76.9(B)
NetR382_1: R382.1 U77.15(FORCEON)
NetR385_1: R385.1 U77.14(~{FORCEOFF})

Not connected (* = marked no-connect by the designer): J67 1* 4* 6* 9*; U45 1(NC)*; U77 7(NC)* 8(NC)* 13(~{INVALID})*

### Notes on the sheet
- RS-232
- Autopowerdown Select
- 1-2: AutoPowerdown plus disabled
- 2-3: AutoPowerdown plus enabled
- (near J66) Jumper
- RS-485

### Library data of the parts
C302-C310 = 1566-Cap-0402-100nF/50V: as C270 on sheet 160_Power_4
J18 = 1250-Conn-Hdr-1x2 TH Vert: (-40 to 85 DegC) CONN HDR VERT 1x2 2pos 2.54mm 0.1in Gold no-shroud; Mfr: Amphenol FCI; MfrNo: 67996-200HLF; PN: 1250
J20 = 2094-Conn-Hdr 1x2 2POS 5MM SCREW TERM: (-30 to 120 DegC) CONN TERM BLK 2POS SIDE ENTRY 5MM SCREW 16A 300V; Mfr: Wurth Electronics; PN: 2094
J66 = 1250-Conn-Hdr-1x2 TH Vert: as J68 on sheet 510_ISO_CAN
J67 = 0760-Conn-DSUB9 Male R/A: (-55 to 105 DegC) CONN D-SUB PLUG 9POS R/A SOLDER Male; MfrNo: A-DS 09 A/KG-T2S; Mfr: Assmann WSW Components; PN: 760
J87 = 2539-Conn-Hdr-1x3 TH Vert: (-65 to 125 DegC) CONN HDR VERT 3x1 3pos 2.54mm 0.1in Gold no-shroud; Mfr: Amphenol ICC / FCI; PN: 2539
L78-L80 = 0405-Fer-0603-330ohm/1.7A: as L71 on sheet 510_ISO_CAN
R343 R345 R382-R385 R432 = 1572-Res-0402-10K: (-55 to 155 DegC AEC) RES 10K OHM 1% 1/16W 100ppm 0402; Mfr: Stackpole Electronics; MfrNo: RMCF0402FT10K0; Alt: AC0402FR-0710KL,AC0402FR-1310KL,CRGCQ0402F10K; PN: 1572
R344 = 1977-Res-0402-100K: as R307 on sheet 160_Power_4
R346 R407 = 0000-Res-0603-DNP: RES 0603
R348 R349 = 0257-Res-0402-10ohm: (-55 to 155 DegC) RES 10 OHM 1/16W 1% 0402 SMD; Mfr: Rohm Semiconductor; MfrNo: MCR01MRTF10R0; Alt: 311-10.0LRCT-ND; Alt2: 1276-3428-1-ND; PN: 257
R350 = 1552-Res-0402-120: (-55 to 155 DegC AEC) RES 120 OHM 1% 1/16W 100ppm 0402; Mfr: Stackpole Electronics; MfrNo: RMCF0402FT120R; PN: 1552; Alt: AC0402FR-07120RL,CRGCQ0402F120R
U45 = 2009-74LVC1G14SE-7: (-40 to 125 DegC) IC INVERTER SCHMITT 1CH 1IN 1.65-5.5V SOT353; Mfr: Diodes; PN: 2009; Desc: (-40 to 125 DegC) IC INVERT SCHMITT 1CH 1IN 1.65-5.5V SOT353
U76 = 2215-SN65HVD01DRCR: (-40 to 125 DegC) IC TRANSCEIVER HALF 1/1, 3V3 RS-485, 1.65V I/O, 10VSON; Mfr: Texas Instruments; PN: 2215
U77 = 2205-TRS3122ERGER: (-40 to 85 DegC) IC TRANSCEIVER RS-232 2/2 24-VQFN (4x4); Mfr: Texas Instruments; PN: 2205; Desc: (-40 to 85 DegC) IC TRANSCEIVER 2/2 24VQFN

## Sheet 315_USBC_DFP.SchDoc: Aquila Development Board
size A3; Organization: Toradex Solutions Inc.; Address1: 6415 Northwest Drive; Address2: Mississauga, ON, L4V 1X1; Address3: Canada; SheetNumber: 17; SheetTotal: 34
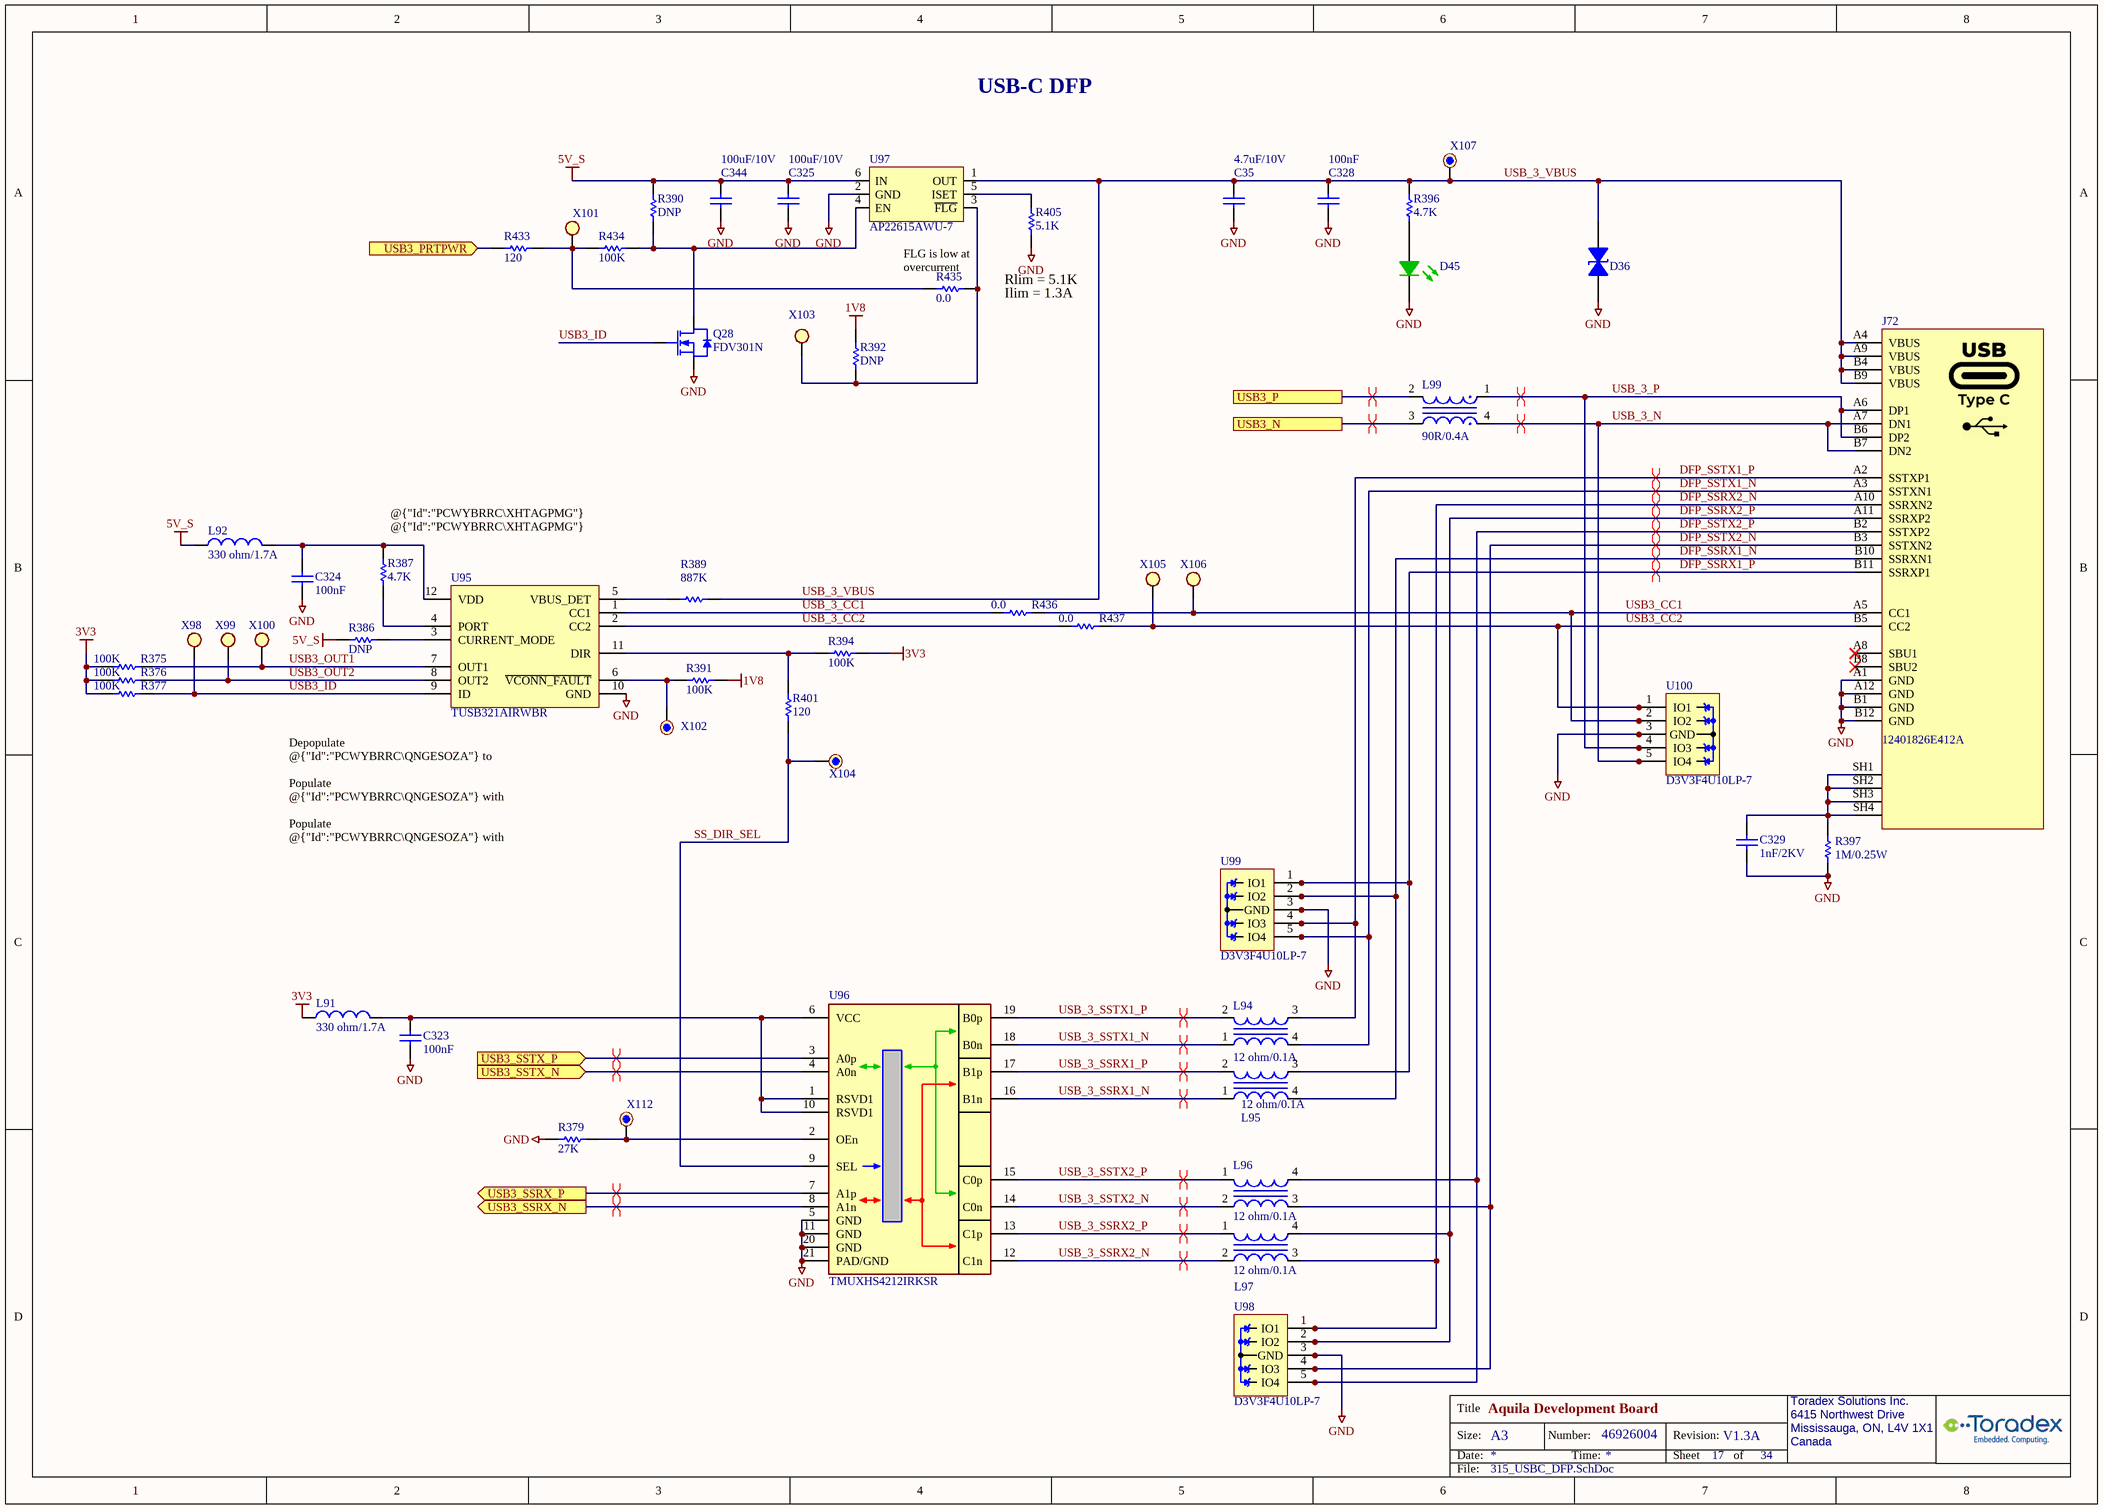
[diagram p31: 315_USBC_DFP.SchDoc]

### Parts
C35  value 4.7uF/10V  [C/0603]  (hidden comment: 2093-Cap-0603-4.7uF/10V)
C323  100nF  [C0402_CAPC1005L]
C324  100nF  [C0402_CAPC1005L]
C325  100uF/10V  [C/1206]
C328  100nF  [C0402_CAPC1005L]
C329  value 1nF/2KV  [C/1206]  (hidden comment: 0567-Cap-1206-1nF/2KV)
C344  100uF/10V  [C/1206]
D36  D5V0L1B2S9-7  [SOD923_DIO]  (value not drawn)
D45  Status  [LED-SMT-0603_APT1608CGCK]  (value not drawn)
J72  12401826E412A  [AMPHENOL_12401826E412A]
L91  value 330 ohm/1.7A  [C/0603]  (hidden comment: 0405-Fer-0603-330ohm/1.7A)
L92  value 330 ohm/1.7A  [C/0603]  (hidden comment: 0405-Fer-0603-330ohm/1.7A)
L94  12 ohm/0.1A  [COIL0302]
L95  12 ohm/0.1A  [COIL0302]
L96  12 ohm/0.1A  [COIL0302]
L97  12 ohm/0.1A  [COIL0302]
L99  90R/0.4A  [COMMON_CHOKE_BOURNS_SRF2012-900YA]
Q28  FDV301N  [SOT23]
R375  value 100K  [R0402_RESC1005L]  (hidden comment: 1977-Res-0402-100K)
R376  value 100K  [R0402_RESC1005L]  (hidden comment: 1977-Res-0402-100K)
R377  value 100K  [R0402_RESC1005L]  (hidden comment: 1977-Res-0402-100K)
R379  value 27K  [R0402_RESC1005L]  (hidden comment: 1538-Res-0402-27k)
R386  value DNP  [R/0603]  (hidden comment: 0000-Res-0603-DNP)
R387  value 4.7K  [R0402_RESC1005L]  (hidden comment: 2233-Res-0402-4.7K)
R389  value 887K  [R0402_RESC1005L]  (hidden comment: 1809-Res-0402-887K)
R390  value DNP  [R/0603]  (hidden comment: 0000-Res-0603-DNP)
R391  value 100K  [R0402_RESC1005L]  (hidden comment: 1977-Res-0402-100K)
R392  value DNP  [R0402_RESC1005L]  (hidden comment: 0000-Res-0402-DNP)
R394  value 100K  [R0402_RESC1005L]  (hidden comment: 1977-Res-0402-100K)
R396  value 4.7K  [R0402_RESC1005L]  (hidden comment: 2233-Res-0402-4.7K)
R397  value 1M/0.25W  [R/1206]  (hidden comment: 1860-Res-1206-1M-5%-0.25W)
R401  value 120  [R0402_RESC1005L]  (hidden comment: 1552-Res-0402-120)
R405  value 5.1K  [R/0603]  (hidden comment: 0227-Res-0603-5.1K)
R433  value 120  [R0402_RESC1005L]  (hidden comment: 1552-Res-0402-120)
R434  value 100K  [R0402_RESC1005L]  (hidden comment: 1977-Res-0402-100K)
R435  value 0.0  [R/0603]  (hidden comment: 0195-Res-0603-0.0ohm)
R436  value 0.0  [R/0603]  (hidden comment: 0195-Res-0603-0.0ohm)
R437  value 0.0  [R/0603]  (hidden comment: 0195-Res-0603-0.0ohm)
U95  TUSB321AIRWBR  [12-X2QFN (1.6x1.6)]
U96  TMUXHS4212IRKSR  [VQFN-20 (4.5x2.5)]
U97  AP22615AWU-7  [TSOT26]
U98  D3V3F4U10LP-7  [10-UFDFN]
U99  D3V3F4U10LP-7  [10-UFDFN]
U100  D3V3F4U10LP-7  [10-UFDFN]
X98  000-TestPoint2  [TestPoint_3]  (value not drawn)
X99  000-TestPoint2  [TestPoint_3]  (value not drawn)
X100  000-TestPoint2  [TestPoint_3]  (value not drawn)
X101  000-TestPoint2  [TestPoint_3]  (value not drawn)
X102  000-TestPoint  [TestPoint_1]  (value not drawn)
X103  000-TestPoint2  [TestPoint_3]  (value not drawn)
X104  000-TestPoint  [TestPoint_1]  (value not drawn)
X105  000-TestPoint2  [TestPoint_3]  (value not drawn)
X106  000-TestPoint2  [TestPoint_3]  (value not drawn)
X107  000-TestPoint  [TestPoint_1]  (value not drawn)
X112  000-TestPoint  [TestPoint_1]  (value not drawn)

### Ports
USB3_N, USB3_P, USB3_PRTPWR (in), USB3_SSRX_N (out), USB3_SSRX_P (out), USB3_SSTX_N (in), USB3_SSTX_P (in)

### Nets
1V8: R391.2 R392.1
3V3: L91.1 R375.2 R376.2 R377.2 R394.2
5V_S: C325.2 C344.2 L92.1 R386.2 R390.2 U97.6(IN)
GND: C35.1 C323.1 C324.1 C325.1 C328.1 C329.1 C344.1 D36.1 D45.2(K) J72.A1(GND) J72.A12(GND) J72.B1(GND) J72.B12(GND) Q28.2(S) R379.1 R397.2 R405.2 U95.10(GND) U96.5(GND) U96.11(GND) U96.20(GND) U96.21(PAD/GND) U97.2(GND) U98.3(GND) U98.8(GND) U99.3(GND) U99.8(GND) U100.3(GND) U100.8(GND)
DFP_SSRX1_N: J72.B10(SSRXN1) L95.4 U99.2(IO2) U99.9(NC)
DFP_SSRX1_P: J72.B11(SSRXP1) L95.3 U99.1(IO1) U99.10(NC)
DFP_SSRX2_N: J72.A10(SSRXN2) L97.3 U98.1(IO1) U98.10(NC)
DFP_SSRX2_P: J72.A11(SSRXP2) L97.4 U98.2(IO2) U98.9(NC)
DFP_SSTX1_N: J72.A3(SSTXN1) L94.4 U99.5(IO4) U99.6(NC)
DFP_SSTX1_P: J72.A2(SSTXP1) L94.3 U99.4(IO3) U99.7(NC)
DFP_SSTX2_N: J72.B3(SSTXN2) L96.3 U98.4(IO3) U98.7(NC)
DFP_SSTX2_P: J72.B2(SSTXP2) L96.4 U98.5(IO4) U98.6(NC)
SS_DIR_SEL: R401.1 U96.9(SEL) X104.1
USB3_CC1: J72.A5(CC1) R436.1 U100.2(IO2) U100.9(NC) X106.1
USB3_CC2: J72.B5(CC2) R437.1 U100.1(IO1) U100.10(NC) X105.1
USB3_ID: Q28.1(G) R377.1 U95.9(ID) X98.1
USB3_N: L99.3 ; port USB3_N
USB3_OUT1: R375.1 U95.7(OUT1) X100.1
USB3_OUT2: R376.1 U95.8(OUT2) X99.1
USB3_P: L99.2 ; port USB3_P
USB3_PRTPWR: R433.2 ; port USB3_PRTPWR
USB3_SSRX_N: U96.8(A1n) ; port USB3_SSRX_N
USB3_SSRX_P: U96.7(A1p) ; port USB3_SSRX_P
USB3_SSTX_N: U96.4(A0n) ; port USB3_SSTX_N
USB3_SSTX_P: U96.3(A0p) ; port USB3_SSTX_P
USB_3_CC1: R436.2 U95.1(CC1)
USB_3_CC2: R437.2 U95.2(CC2)
USB_3_N: J72.A7(DN1) J72.B7(DN2) L99.4 U100.5(IO4) U100.6(NC)
USB_3_P: J72.A6(DP1) J72.B6(DP2) L99.1 U100.4(IO3) U100.7(NC)
USB_3_SSRX1_N: L95.1 U96.16(B1n)
USB_3_SSRX1_P: L95.2 U96.17(B1p)
USB_3_SSRX2_N: L97.2 U96.12(C1n)
USB_3_SSRX2_P: L97.1 U96.13(C1p)
USB_3_SSTX1_N: L94.1 U96.18(B0n)
USB_3_SSTX1_P: L94.2 U96.19(B0p)
USB_3_SSTX2_N: L96.2 U96.14(C0n)
USB_3_SSTX2_P: L96.1 U96.15(C0p)
USB_3_VBUS: C35.2 C328.2 D36.2 J72.A4(VBUS) J72.A9(VBUS) J72.B4(VBUS) J72.B9(VBUS) R389.2 R396.2 U97.1(OUT) X107.1
NetC323_2: C323.2 L91.2 U96.1(RSVD1) U96.6(VCC) U96.10(RSVD1)
NetC324_2: C324.2 L92.2 R387.2 U95.12(VDD)
NetC329_2: C329.2 J72.SH1(SHIELD) J72.SH2(SHIELD) J72.SH3(SHIELD) J72.SH4(SHIELD) R397.1
NetD45_1: D45.1(A) R396.1
NetQ28_3: Q28.3(D) R390.1 R434.2 U97.4(EN)
NetR379_2: R379.2 U96.2(OEn) X112.1
NetR386_1: R386.1 U95.3(CURRENT_MODE)
NetR387_1: R387.1 U95.4(PORT)
NetR389_1: R389.1 U95.5(VBUS_DET)
NetR391_1: R391.1 U95.6(~{VCONN_FAULT}) X102.1
NetR392_2: R392.2 R435.1 U97.3(~{FLG}) X103.1
NetR394_1: R394.1 R401.2 U95.11(DIR)
NetR405_1: R405.1 U97.5(ISET)
NetR433_1: R433.1 R434.1 R435.2 X101.1

Not connected (* = marked no-connect by the designer): J72 A8(SBU1)* B8(SBU2)*

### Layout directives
differential pair; differential pair class USB_3_CON: USB_3_N, USB_3_P
differential pair; differential pair class USB_3: USB3_N, USB3_P
differential pair; differential pair class USB_3_MUX_SS1: USB_3_SSRX1_N, USB_3_SSRX1_P, USB_3_SSTX1_N, USB_3_SSTX1_P
differential pair; differential pair class USB_3_MUX_SS2: USB_3_SSRX2_N, USB_3_SSRX2_P, USB_3_SSTX2_N, USB_3_SSTX2_P
differential pair; differential pair class DFP_SSTX1: DFP_SSTX1_N, DFP_SSTX1_P
differential pair; differential pair class DFP_SSRX2: DFP_SSRX2_N
differential pair; differential pair class DFP_SSRX1: DFP_SSRX1_N, DFP_SSRX1_P, DFP_SSRX2_P
differential pair; differential pair class DFP_SSTX2: DFP_SSTX2_N, DFP_SSTX2_P
differential pair; differential pair class USB_3_SSRX: USB3_SSRX_N, USB3_SSRX_P
differential pair; differential pair class USB_3_SSTX: USB3_SSTX_N, USB3_SSTX_P

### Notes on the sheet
- USB-C DFP
- FLG is low at
- (near R435) overcurrent
- Rlim = 5.1K
- Ilim = 1.3A
- (near R387) @{"Id":"PCWYBRRC\XHTAGPMG"} -> DFP if populated
- (near R387) @{"Id":"PCWYBRRC\XHTAGPMG"} -> DRP if unpopulated
- (near U95) Depopulate @{"Id":"PCWYBRRC\QNGESOZA"} to advertise 0.9A
  Populate @{"Id":"PCWYBRRC\AUISDQWD"} with 5.1k for ISET = 1.3A
- Populate @{"Id":"PCWYBRRC\QNGESOZA"} with 500k to advertise 1.5A
  Populate @{"Id":"PCWYBRRC\AUISDQWD"} with 4k for ISET = 1.7A
- Populate @{"Id":"PCWYBRRC\QNGESOZA"} with 10k to advertise 3A
  Populate @{"Id":"PCWYBRRC\AUISDQWD"} with 2k for ISET = 3.4A

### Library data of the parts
C35 = 2093-Cap-0603-4.7uF/10V: (-55 to 85 DegC) CAP CER 4.7UF 10V 20% X5R 0603; Mfr: Samsung; MfrNo: CL10A475KP8NNNC; PN: 2093
C323 C324 C328 = 1566-Cap-0402-100nF/50V: as C270 on sheet 160_Power_4
C325 C344 = 2282-Cap-1206-100uF/10V: (-55 to 85 DegC) CAP CER 100UF 10V 20% X5R 1206; MfrNo: GRM31CR61A107MEA8L; Mfr: Murata; PN: 2282
C329 = 0567-Cap-1206-1nF/2KV: as C288 on sheet 325_USB_PowerDelivery
D36 = 1655-D5V0L1B2S9-7: as D43 on sheet 160_Power_4
D45 = 0333-LED Green 0603: as D49 on sheet 160_Power_4
J72 = 1512-Conn-USB-Type-C: (-40 to 85 DegC) Conn USB TYPE C RA SMT; Mfr: Amphenol Communications Solutions; PN: 1512
L91 L92 = 0405-Fer-0603-330ohm/1.7A: as L71 on sheet 510_ISO_CAN
L94-L97 = 1371-Ind-0.8x0.6-12ohm/0.1A-Choke: (-40 to 85 DegC) Ind CMC Choke 12 Ohm 0.1A 1ohm 0.85x0.65x0.5mm; MfrNo: EXC-14CH120U; Mfr: Panasonic; PN: 1371
L99 = 0277-Ind-2x1.2-90ohm/0.4A-Choke: (-40 to 125 DegC) INDUCTOR COMMON MODE 90 OHM 0.4A 0.3ohm; MfrNo: SRF2012-900YA; Mfr: Bourns Inc.; PN: 277; Alt: 445-2207-1-ND
Q28 = 0761-FDV301N: as Q21 on sheet 325_USB_PowerDelivery
R375-R377 R391 R394 R434 = 1977-Res-0402-100K: as R307 on sheet 160_Power_4
R379 = 1538-Res-0402-27k: as R335 on sheet 325_USB_PowerDelivery
R386 R390 = 0000-Res-0603-DNP: RES 0603
R387 R396 = 2233-Res-0402-4.7K: as R312 on sheet 160_Power_4
R389 = 1809-Res-0402-887K: (-55 to 155 DegC AEC) RES 887K OHM 1% 1/16W 100ppm 0402; MfrNo: RMCF0402FT887K; Mfr: Stackpole Electronics; PN: 1809
R392 = 0000-Res-0402-DNP: RES 0402
R397 = 1860-Res-1206-1M-5%-0.25W: as R319 on sheet 325_USB_PowerDelivery
R401 R433 = 1552-Res-0402-120: as R380 on sheet 510_ISO_CAN
R405 = 0227-Res-0603-5.1K: (-55 to 155 DegC) RES 5.1K OHM 1/10W 1% 0603 SMD; Mfr: Rohm; MfrNo: MCR03ERTF5101; PN: 227; Alt: 1276-4713-1-ND; Alt2: 311-5.10KHRCT-ND
R435-R437 = 0195-Res-0603-0.0ohm: as R329 on sheet 325_USB_PowerDelivery
U95 = 2212-TUSB321AIRWBR: (-40 to 85 DegC) IC USB TYPE-C CC LOGIC W/ DIR PIN 12-XFQFN; Mfr: Texas Instruments; PN: 2212
U96 = 2263-TMUXHS4212IRKSR: (-40 to 105 DegC) IC SWITCH MULTIPLEXER 2:1 DPST, SPDT X 2 3.3V/1.8V 20VQFN; Mfr: Texas Instruments; PN: 2263
U97 = 2238-AP22615AWU-7: (-40 to 85 DegC) IC PWR SWITCH 3-5.5V EN-Active-High ENth:1.2V With-Discharge 40mohm typ ADJ 0.4-4A TSOT-26; Mfr: Diodes; PN: 2238
U98-U100 = 1463-D3V3F4U10LP: (-55 to 150 DegC) IC TVS DIODE 4ch Vrm:3.3V Vbr:6.2 Vcl:5V@16A 12KV/12KV 0.5pF 10-UFDFN 0.5mm; Mfr: Diodes; PN: 1463; Notes: Similar: PN1317
X98-X101 X103 X105 X106 = 000-TestPoint2: as X87 on sheet 160_Power_4
X102 X104 X107 X112 = 000-TestPoint: as X86 on sheet 160_Power_4

## Sheet 445_CSI_1.SchDoc: Aquila Development Board
size Letter; Organization: Toradex Solutions Inc.; Address1: 6415 Northwest Drive; Address2: Mississauga, ON, L4V 1X1; Address3: Canada; SheetNumber: 24; SheetTotal: 34
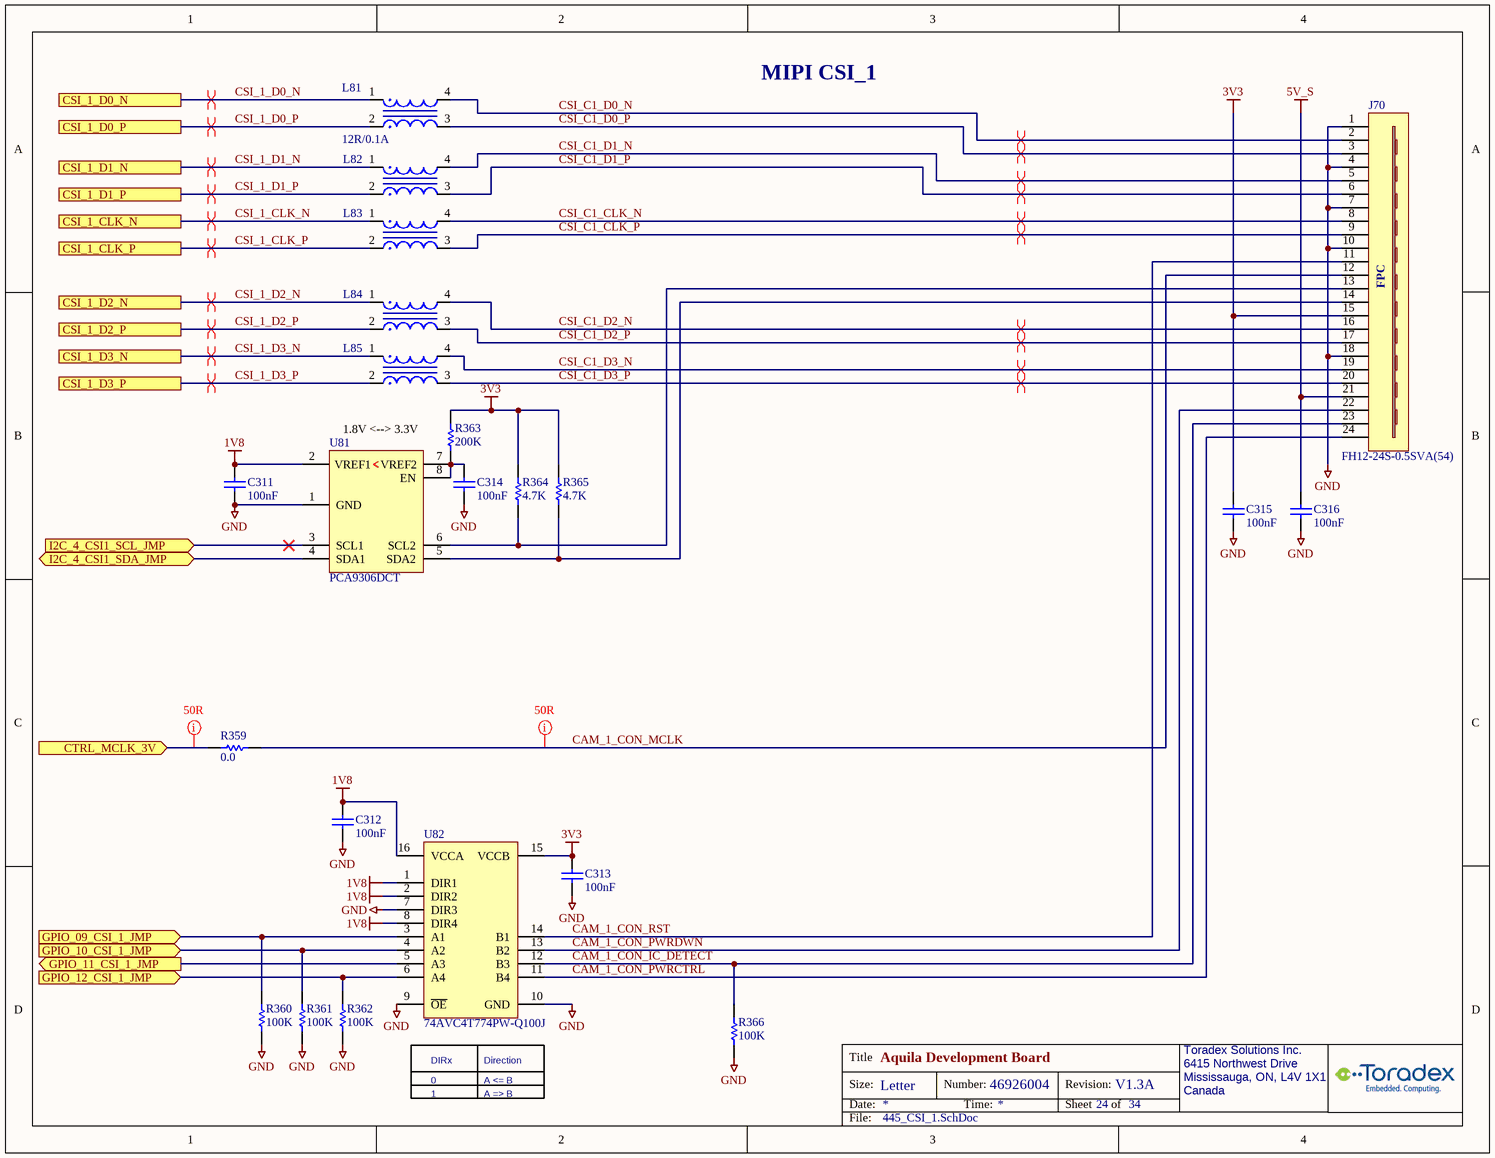
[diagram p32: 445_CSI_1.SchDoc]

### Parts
C311  100nF  [C0402_CAPC1005L]
C312  100nF  [C0402_CAPC1005L]
C313  100nF  [C0402_CAPC1005L]
C314  100nF  [C0402_CAPC1005L]
C315  100nF  [C0402_CAPC1005L]
C316  100nF  [C0402_CAPC1005L]
J70  FH12-24S-0.5SVA(54)  [HIROSE_FH12-24S-0.5SVA(54)]
L81  12R/0.1A  [COIL0302]
L82  12R/0.1A  [COIL0302]  (value not drawn)
L83  12R/0.1A  [COIL0302]  (value not drawn)
L84  12R/0.1A  [COIL0302]  (value not drawn)
L85  12R/0.1A  [COIL0302]  (value not drawn)
R359  value 0.0  [R/0603]  (hidden comment: 0195-Res-0603-0.0ohm)
R360  value 100K  [R0402_RESC1005L]  (hidden comment: 1977-Res-0402-100K)
R361  value 100K  [R0402_RESC1005L]  (hidden comment: 1977-Res-0402-100K)
R362  value 100K  [R0402_RESC1005L]  (hidden comment: 1977-Res-0402-100K)
R363  value 200K  [R0402_RESC1005L]  (hidden comment: 1540-Res-0402-200k)
R364  value 4.7K  [R0402_RESC1005L]  (hidden comment: 2233-Res-0402-4.7K)
R365  value 4.7K  [R0402_RESC1005L]  (hidden comment: 2233-Res-0402-4.7K)
R366  value 100K  [R0402_RESC1005L]  (hidden comment: 1977-Res-0402-100K)
U81  PCA9306DCT  [TSSO3x5-G8/X.35]
U82  74AVC4T774PW-Q100J  [TSSOP16_NXP]

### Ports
CSI_1_CLK_N, CSI_1_CLK_P, CSI_1_D0_N, CSI_1_D0_P, CSI_1_D1_N, CSI_1_D1_P, CSI_1_D2_N, CSI_1_D2_P, CSI_1_D3_N, CSI_1_D3_P, CTRL_MCLK_3V (in), GPIO_09_CSI_1_JMP (in), GPIO_10_CSI_1_JMP (in), GPIO_11_CSI_1_JMP (out), GPIO_12_CSI_1_JMP (in), I2C_4_CSI1_SCL_JMP (in), I2C_4_CSI1_SDA_JMP (bidir)

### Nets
1V8: C311.2 C312.2 U81.2(VREF1) U82.1(DIR1) U82.2(DIR2) U82.8(DIR4) U82.16(VCCA)
3V3: C313.2 C315.2 J70.15 R363.1 R364.1 R365.1 U82.15(VCCB)
5V_S: C316.2 J70.21
GND: C311.1 C312.1 C313.1 C314.1 C315.1 C316.1 J70.1 J70.4 J70.7 J70.10 J70.18 R360.1 R361.1 R362.1 R366.1 U81.1(GND) U82.7(DIR3) U82.9(~{OE}) U82.10(GND)
CAM_1_CON_IC_DETECT: J70.23 R366.2 U82.12(B3)
CAM_1_CON_MCLK: J70.12 R359.1
CAM_1_CON_PWRCTRL: J70.24 U82.11(B4)
CAM_1_CON_PWRDWN: J70.22 U82.13(B2)
CAM_1_CON_RST: J70.11 U82.14(B1)
CSI_1_CLK_N: L83.1 ; port CSI_1_CLK_N
CSI_1_CLK_P: L83.2 ; port CSI_1_CLK_P
CSI_1_D0_N: L81.1 ; port CSI_1_D0_N
CSI_1_D0_P: L81.2 ; port CSI_1_D0_P
CSI_1_D1_N: L82.1 ; port CSI_1_D1_N
CSI_1_D1_P: L82.2 ; port CSI_1_D1_P
CSI_1_D2_N: L84.1 ; port CSI_1_D2_N
CSI_1_D2_P: L84.2 ; port CSI_1_D2_P
CSI_1_D3_N: L85.1 ; port CSI_1_D3_N
CSI_1_D3_P: L85.2 ; port CSI_1_D3_P
CSI_C1_CLK_N: J70.8 L83.4
CSI_C1_CLK_P: J70.9 L83.3
CSI_C1_D0_N: J70.2 L81.4
CSI_C1_D0_P: J70.3 L81.3
CSI_C1_D1_N: J70.5 L82.4
CSI_C1_D1_P: J70.6 L82.3
CSI_C1_D2_N: J70.16 L84.4
CSI_C1_D2_P: J70.17 L84.3
CSI_C1_D3_N: J70.19 L85.4
CSI_C1_D3_P: J70.20 L85.3
CTRL_MCLK_3V: R359.2 ; port CTRL_MCLK_3V
GPIO_09_CSI_1_JMP: R360.2 U82.3(A1) ; port GPIO_09_CSI_1_JMP
GPIO_10_CSI_1_JMP: R361.2 U82.4(A2) ; port GPIO_10_CSI_1_JMP
GPIO_11_CSI_1_JMP: U82.5(A3) ; port GPIO_11_CSI_1_JMP
GPIO_12_CSI_1_JMP: R362.2 U82.6(A4) ; port GPIO_12_CSI_1_JMP
I2C_4_CSI1_SCL_JMP: U81.3(SCL1) ; port I2C_4_CSI1_SCL_JMP
I2C_4_CSI1_SDA_JMP: U81.4(SDA1) ; port I2C_4_CSI1_SDA_JMP
NetC314_2: C314.2 R363.2 U81.7(VREF2) U81.8(EN)
NetJ70_13: J70.13 R364.2 U81.6(SCL2)
NetJ70_14: J70.14 R365.2 U81.5(SDA2)

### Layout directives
differential pair; differential pair class CSI_1: CSI_1_CLK_N, CSI_1_CLK_P, CSI_1_D0_N, CSI_1_D0_P, CSI_1_D1_N, CSI_1_D1_P, CSI_1_D2_N, CSI_1_D2_P, CSI_1_D3_N, CSI_1_D3_P
differential pair; differential pair class CSI_1_CON: CSI_C1_CLK_N, CSI_C1_CLK_P, CSI_C1_D0_N, CSI_C1_D0_P, CSI_C1_D1_N, CSI_C1_D1_P, CSI_C1_D2_N, CSI_C1_D2_P, CSI_C1_D3_N, CSI_C1_D3_P
net class 50R: CAM_1_CON_MCLK, CTRL_MCLK_3V

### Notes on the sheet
- MIPI CSI_1
- 1.8V <--> 3.3V
- 0
- (near U82) DIRx
- 1
- (near U82) Direction
- A <= B
- A => B

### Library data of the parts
C311-C316 = 1566-Cap-0402-100nF/50V: as C270 on sheet 160_Power_4
J70 = 1461-Conn-FFC-24pin-0.5mm-Vert: (-40 to 85 DegC) CONN FFC VERT 24POS 0.50MM SMD; Mfr: Hirose; PN: 1461; Notes: Used for MIPI CSI Adapters
L81-L85 = 1371-Ind-0.8x0.6-12ohm/0.1A-Choke: as L94-L97 on sheet 315_USBC_DFP
R359 = 0195-Res-0603-0.0ohm: as R329 on sheet 325_USB_PowerDelivery
R360-R362 R366 = 1977-Res-0402-100K: as R307 on sheet 160_Power_4
R363 = 1540-Res-0402-200k: (-55 to 155 DegC AEC) RES 200K OHM 1% 1/16W 100ppm 0402; Mfr: Stackpole Electronics; MfrNo: RMCF0402FT200K; Alt: AC0402FR-07200KL,AC0402FR-7W200KL,ERJ-2RKF2003X; PN: 1540
R364 R365 = 2233-Res-0402-4.7K: as R312 on sheet 160_Power_4
U81 = 0972-PCA9306DCT: (-40 to 85 DegC) IC TRANSLTR BIDIRECTIONAL I2C SM8; MfrNo: PCA9306DCTR; Mfr: Texas Instruments; PN: 972
U82 = 1597-74AVC4T774: (-40 to 125 DegC AEC) IC Translator 4ch BiDirer 0.8 to 3.6V 380MBps 16TSSOP; Mfr: Nexperia; PN: 1597; Alt: 74AVC4T774PWJ

## Sheet 450_CSI_2.SchDoc: Aquila Development Board
size Letter; Organization: Toradex Solutions Inc.; Address1: 6415 Northwest Drive; Address2: Mississauga, ON, L4V 1X1; Address3: Canada; SheetNumber: 25; SheetTotal: 34
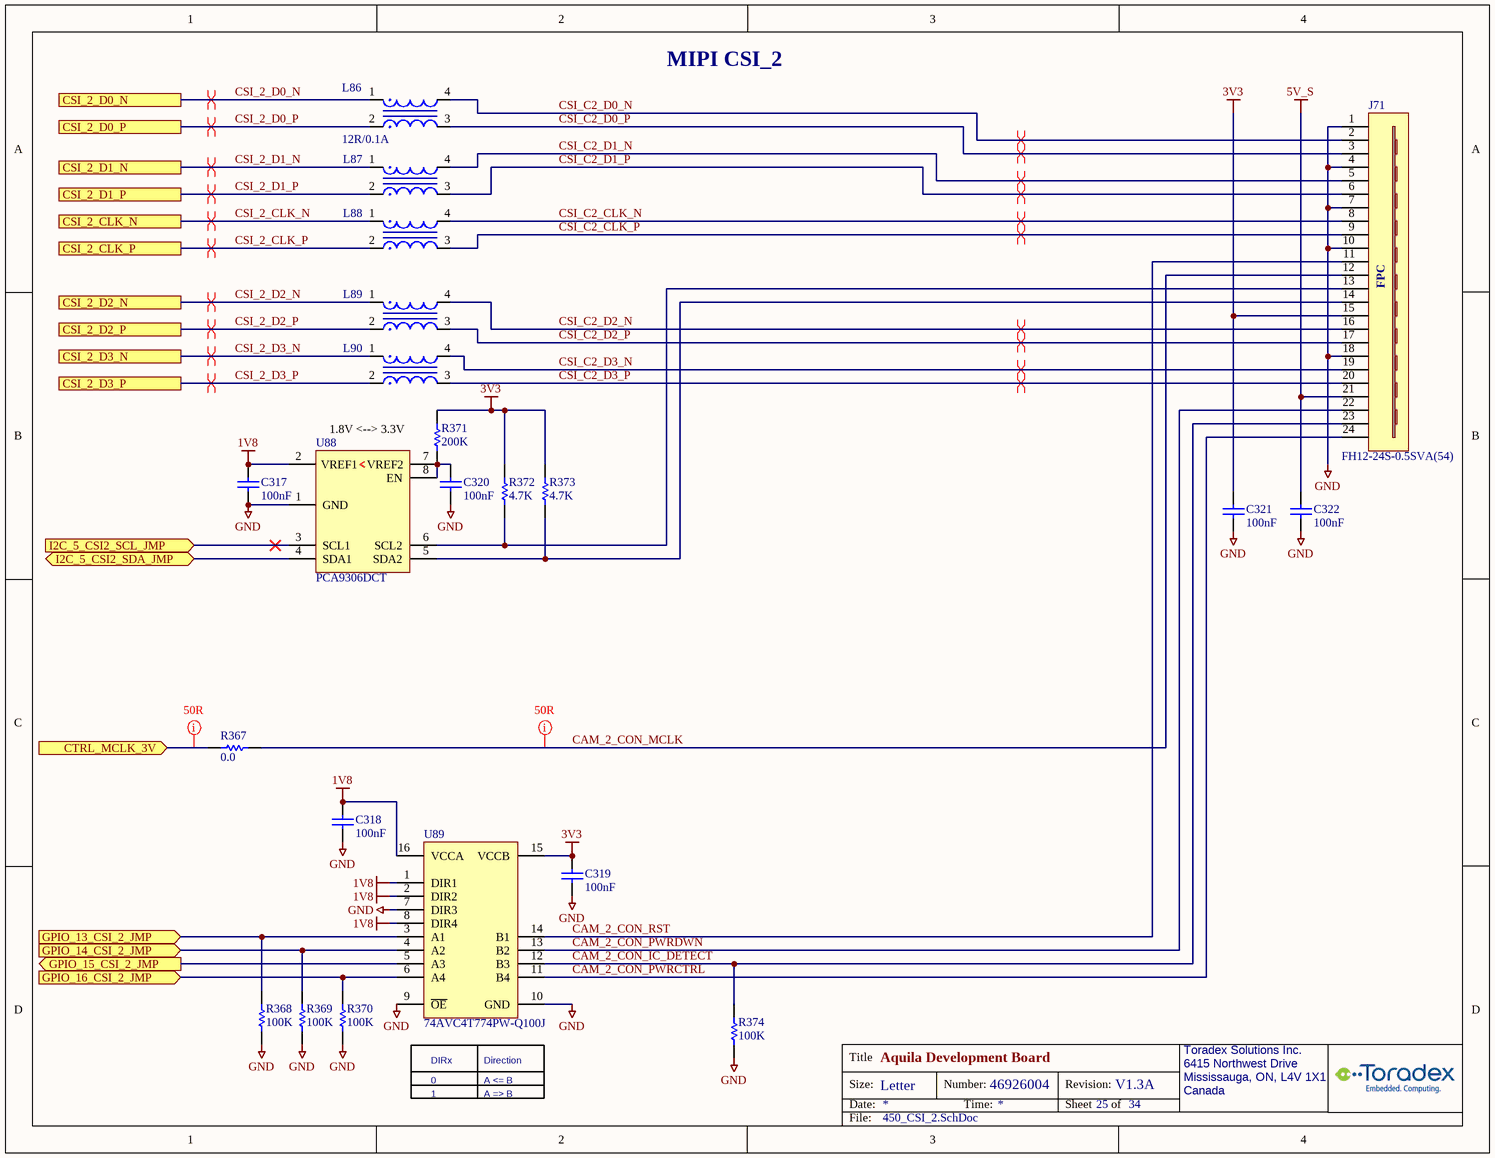
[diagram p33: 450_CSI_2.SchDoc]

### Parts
C317  100nF  [C0402_CAPC1005L]
C318  100nF  [C0402_CAPC1005L]
C319  100nF  [C0402_CAPC1005L]
C320  100nF  [C0402_CAPC1005L]
C321  100nF  [C0402_CAPC1005L]
C322  100nF  [C0402_CAPC1005L]
J71  FH12-24S-0.5SVA(54)  [HIROSE_FH12-24S-0.5SVA(54)]
L86  12R/0.1A  [COIL0302]
L87  12R/0.1A  [COIL0302]  (value not drawn)
L88  12R/0.1A  [COIL0302]  (value not drawn)
L89  12R/0.1A  [COIL0302]  (value not drawn)
L90  12R/0.1A  [COIL0302]  (value not drawn)
R367  value 0.0  [R/0603]  (hidden comment: 0195-Res-0603-0.0ohm)
R368  value 100K  [R0402_RESC1005L]  (hidden comment: 1977-Res-0402-100K)
R369  value 100K  [R0402_RESC1005L]  (hidden comment: 1977-Res-0402-100K)
R370  value 100K  [R0402_RESC1005L]  (hidden comment: 1977-Res-0402-100K)
R371  value 200K  [R0402_RESC1005L]  (hidden comment: 1540-Res-0402-200k)
R372  value 4.7K  [R0402_RESC1005L]  (hidden comment: 2233-Res-0402-4.7K)
R373  value 4.7K  [R0402_RESC1005L]  (hidden comment: 2233-Res-0402-4.7K)
R374  value 100K  [R0402_RESC1005L]  (hidden comment: 1977-Res-0402-100K)
U88  PCA9306DCT  [TSSO3x5-G8/X.35]
U89  74AVC4T774PW-Q100J  [TSSOP16_NXP]

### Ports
CSI_2_CLK_N, CSI_2_CLK_P, CSI_2_D0_N, CSI_2_D0_P, CSI_2_D1_N, CSI_2_D1_P, CSI_2_D2_N, CSI_2_D2_P, CSI_2_D3_N, CSI_2_D3_P, CTRL_MCLK_3V (in), GPIO_13_CSI_2_JMP (in), GPIO_14_CSI_2_JMP (in), GPIO_15_CSI_2_JMP (out), GPIO_16_CSI_2_JMP (in), I2C_5_CSI2_SCL_JMP (in), I2C_5_CSI2_SDA_JMP (bidir)

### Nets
1V8: C317.2 C318.2 U88.2(VREF1) U89.1(DIR1) U89.2(DIR2) U89.8(DIR4) U89.16(VCCA)
3V3: C319.2 C321.2 J71.15 R371.1 R372.1 R373.1 U89.15(VCCB)
5V_S: C322.2 J71.21
GND: C317.1 C318.1 C319.1 C320.1 C321.1 C322.1 J71.1 J71.4 J71.7 J71.10 J71.18 R368.1 R369.1 R370.1 R374.1 U88.1(GND) U89.7(DIR3) U89.9(~{OE}) U89.10(GND)
CAM_2_CON_IC_DETECT: J71.23 R374.2 U89.12(B3)
CAM_2_CON_MCLK: J71.12 R367.1
CAM_2_CON_PWRCTRL: J71.24 U89.11(B4)
CAM_2_CON_PWRDWN: J71.22 U89.13(B2)
CAM_2_CON_RST: J71.11 U89.14(B1)
CSI_2_CLK_N: L88.1 ; port CSI_2_CLK_N
CSI_2_CLK_P: L88.2 ; port CSI_2_CLK_P
CSI_2_D0_N: L86.1 ; port CSI_2_D0_N
CSI_2_D0_P: L86.2 ; port CSI_2_D0_P
CSI_2_D1_N: L87.1 ; port CSI_2_D1_N
CSI_2_D1_P: L87.2 ; port CSI_2_D1_P
CSI_2_D2_N: L89.1 ; port CSI_2_D2_N
CSI_2_D2_P: L89.2 ; port CSI_2_D2_P
CSI_2_D3_N: L90.1 ; port CSI_2_D3_N
CSI_2_D3_P: L90.2 ; port CSI_2_D3_P
CSI_C2_CLK_N: J71.8 L88.4
CSI_C2_CLK_P: J71.9 L88.3
CSI_C2_D0_N: J71.2 L86.4
CSI_C2_D0_P: J71.3 L86.3
CSI_C2_D1_N: J71.5 L87.4
CSI_C2_D1_P: J71.6 L87.3
CSI_C2_D2_N: J71.16 L89.4
CSI_C2_D2_P: J71.17 L89.3
CSI_C2_D3_N: J71.19 L90.4
CSI_C2_D3_P: J71.20 L90.3
CTRL_MCLK_3V: R367.2 ; port CTRL_MCLK_3V
GPIO_13_CSI_2_JMP: R368.2 U89.3(A1) ; port GPIO_13_CSI_2_JMP
GPIO_14_CSI_2_JMP: R369.2 U89.4(A2) ; port GPIO_14_CSI_2_JMP
GPIO_15_CSI_2_JMP: U89.5(A3) ; port GPIO_15_CSI_2_JMP
GPIO_16_CSI_2_JMP: R370.2 U89.6(A4) ; port GPIO_16_CSI_2_JMP
I2C_5_CSI2_SCL_JMP: U88.3(SCL1) ; port I2C_5_CSI2_SCL_JMP
I2C_5_CSI2_SDA_JMP: U88.4(SDA1) ; port I2C_5_CSI2_SDA_JMP
NetC320_2: C320.2 R371.2 U88.7(VREF2) U88.8(EN)
NetJ71_13: J71.13 R372.2 U88.6(SCL2)
NetJ71_14: J71.14 R373.2 U88.5(SDA2)

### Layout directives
differential pair; differential pair class CSI_2: CSI_2_CLK_N, CSI_2_CLK_P, CSI_2_D0_N, CSI_2_D0_P, CSI_2_D1_N, CSI_2_D1_P, CSI_2_D2_N, CSI_2_D2_P, CSI_2_D3_N, CSI_2_D3_P
differential pair; differential pair class CSI_2_CON: CSI_C2_CLK_N, CSI_C2_CLK_P, CSI_C2_D0_N, CSI_C2_D0_P, CSI_C2_D1_N, CSI_C2_D1_P, CSI_C2_D2_N, CSI_C2_D2_P, CSI_C2_D3_N, CSI_C2_D3_P
net class 50R: CAM_2_CON_MCLK, CTRL_MCLK_3V

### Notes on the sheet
- MIPI CSI_2
- 1.8V <--> 3.3V
- 0
- (near U89) DIRx
- 1
- (near U89) Direction
- A <= B
- A => B

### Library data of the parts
C317-C322 = 1566-Cap-0402-100nF/50V: as C270 on sheet 160_Power_4
J71 = 1461-Conn-FFC-24pin-0.5mm-Vert: as J70 on sheet 445_CSI_1
L86-L90 = 1371-Ind-0.8x0.6-12ohm/0.1A-Choke: as L94-L97 on sheet 315_USBC_DFP
R367 = 0195-Res-0603-0.0ohm: as R329 on sheet 325_USB_PowerDelivery
R368-R370 R374 = 1977-Res-0402-100K: as R307 on sheet 160_Power_4
R371 = 1540-Res-0402-200k: as R363 on sheet 445_CSI_1
R372 R373 = 2233-Res-0402-4.7K: as R312 on sheet 160_Power_4
U88 = 0972-PCA9306DCT: as U81 on sheet 445_CSI_1
U89 = 1597-74AVC4T774: as U82 on sheet 445_CSI_1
